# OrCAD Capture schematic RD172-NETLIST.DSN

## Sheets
1 7: size A3
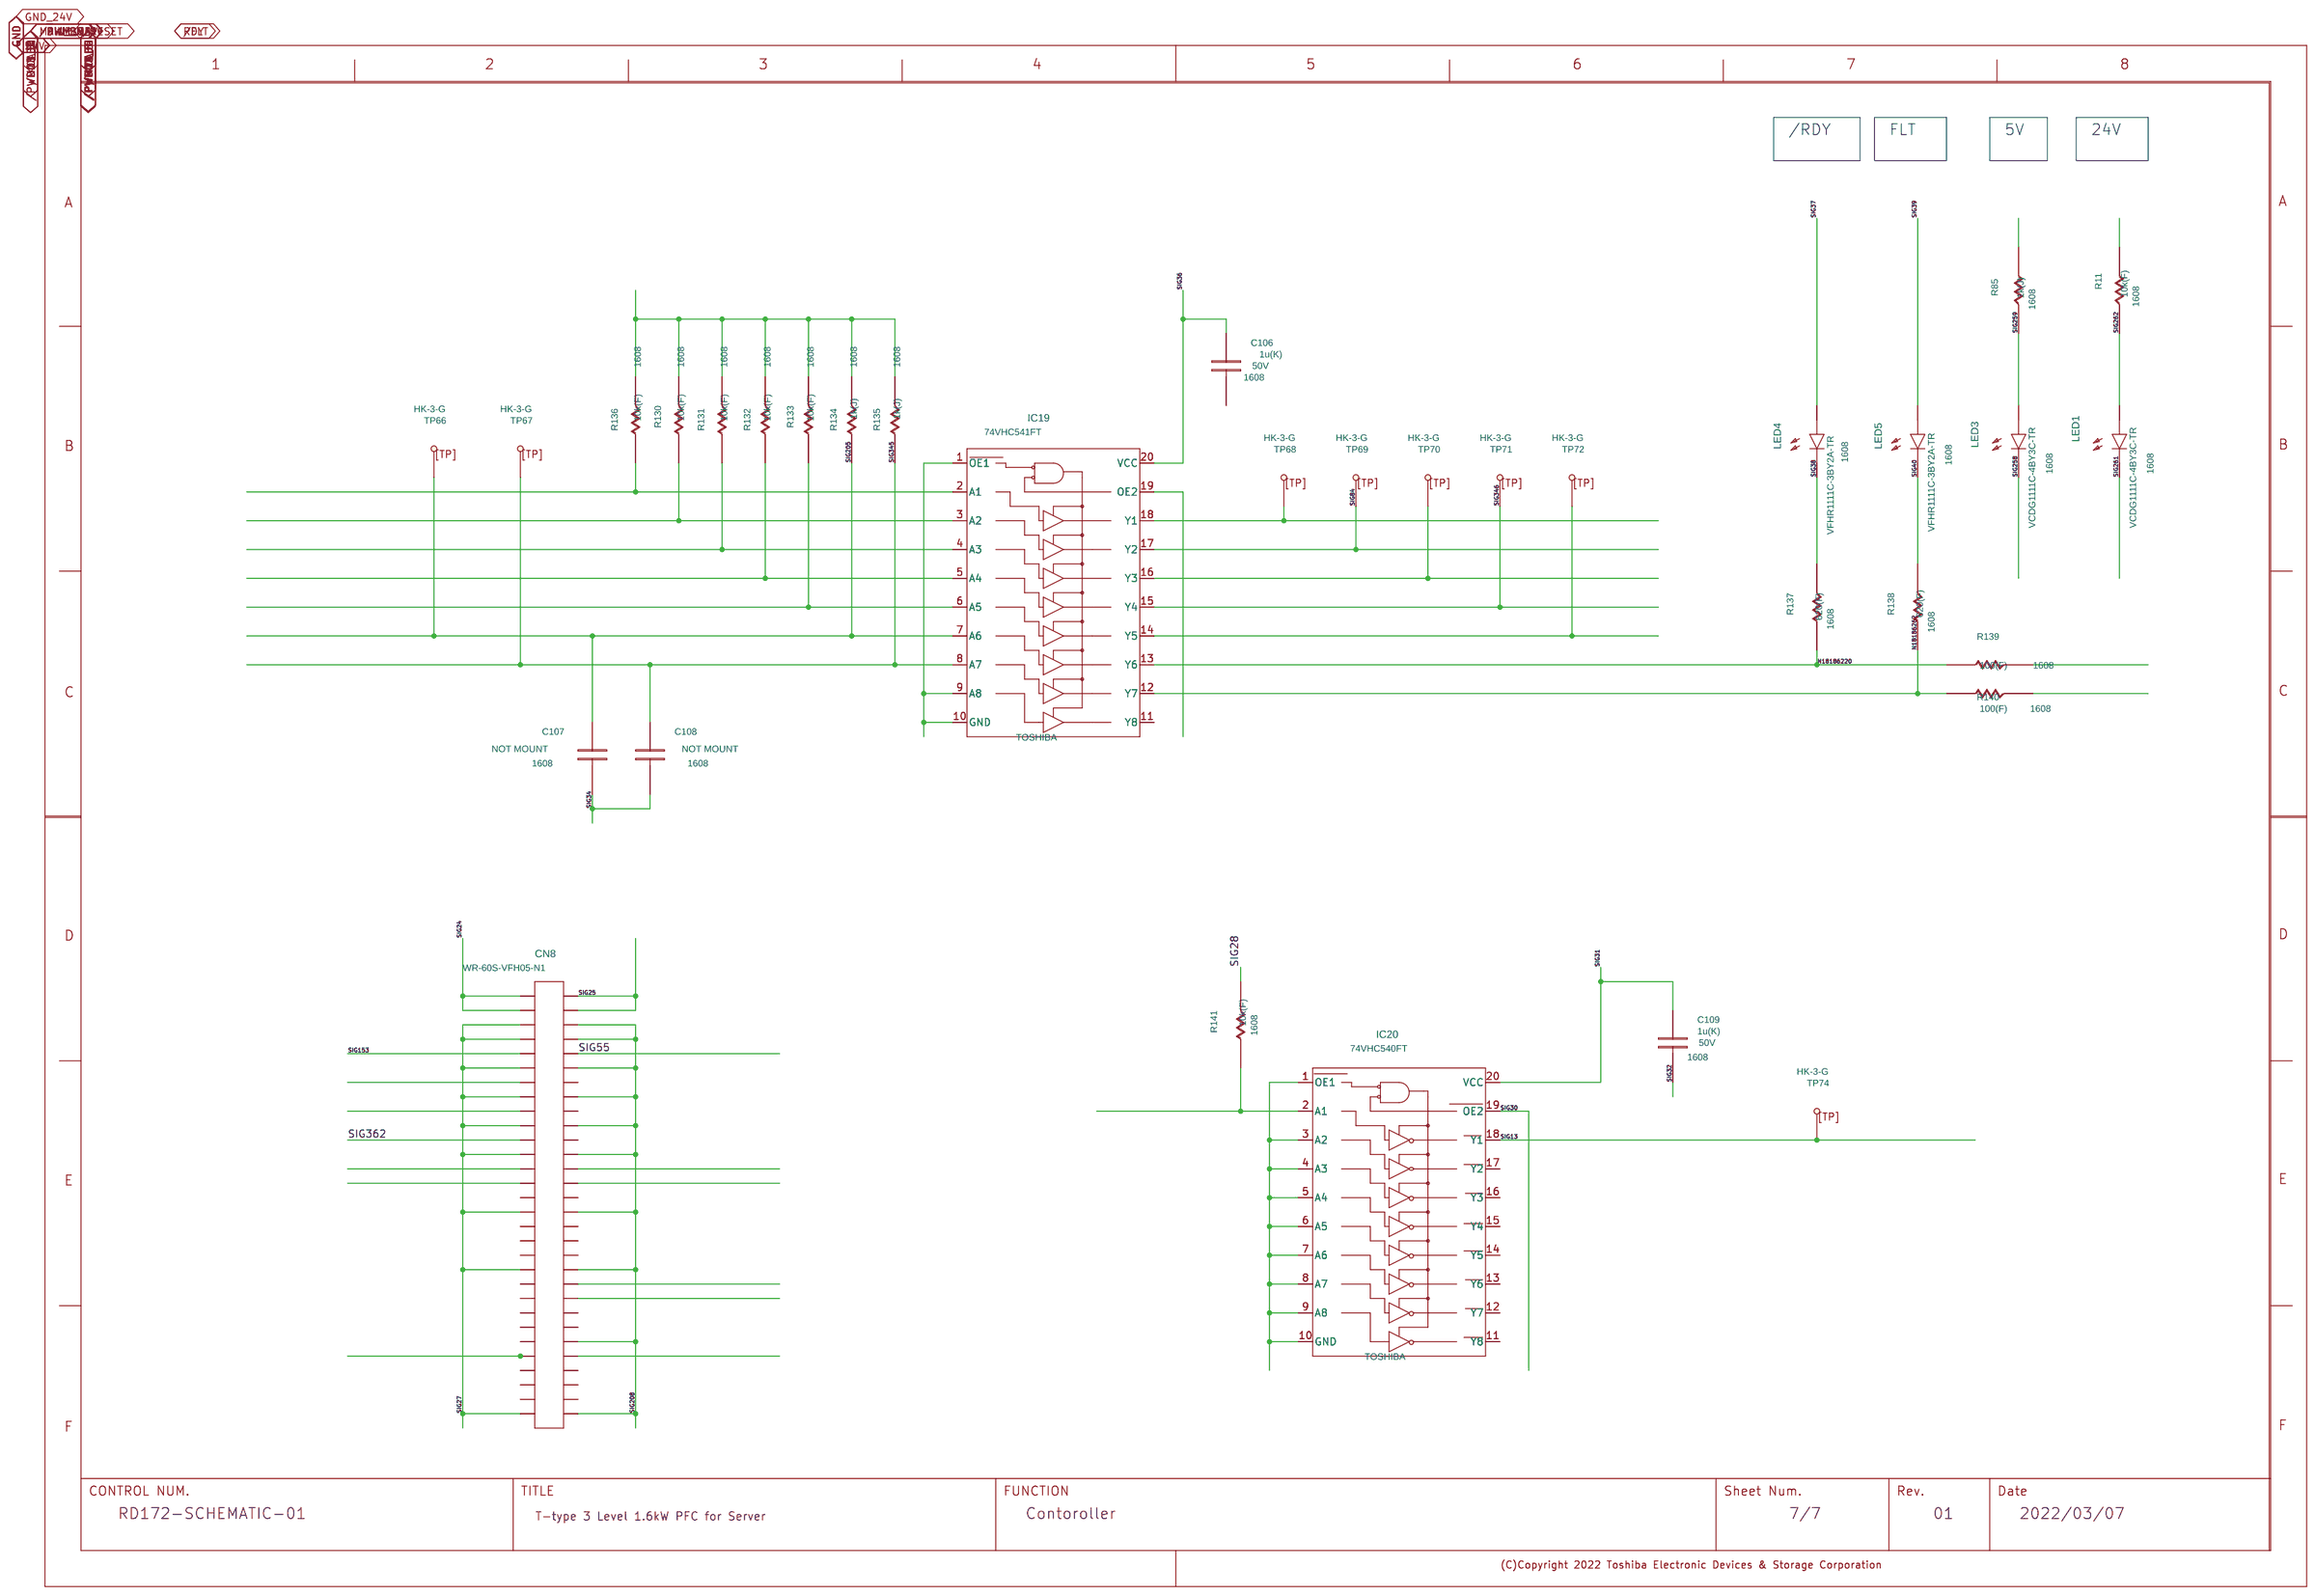
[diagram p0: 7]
2 6: size A3
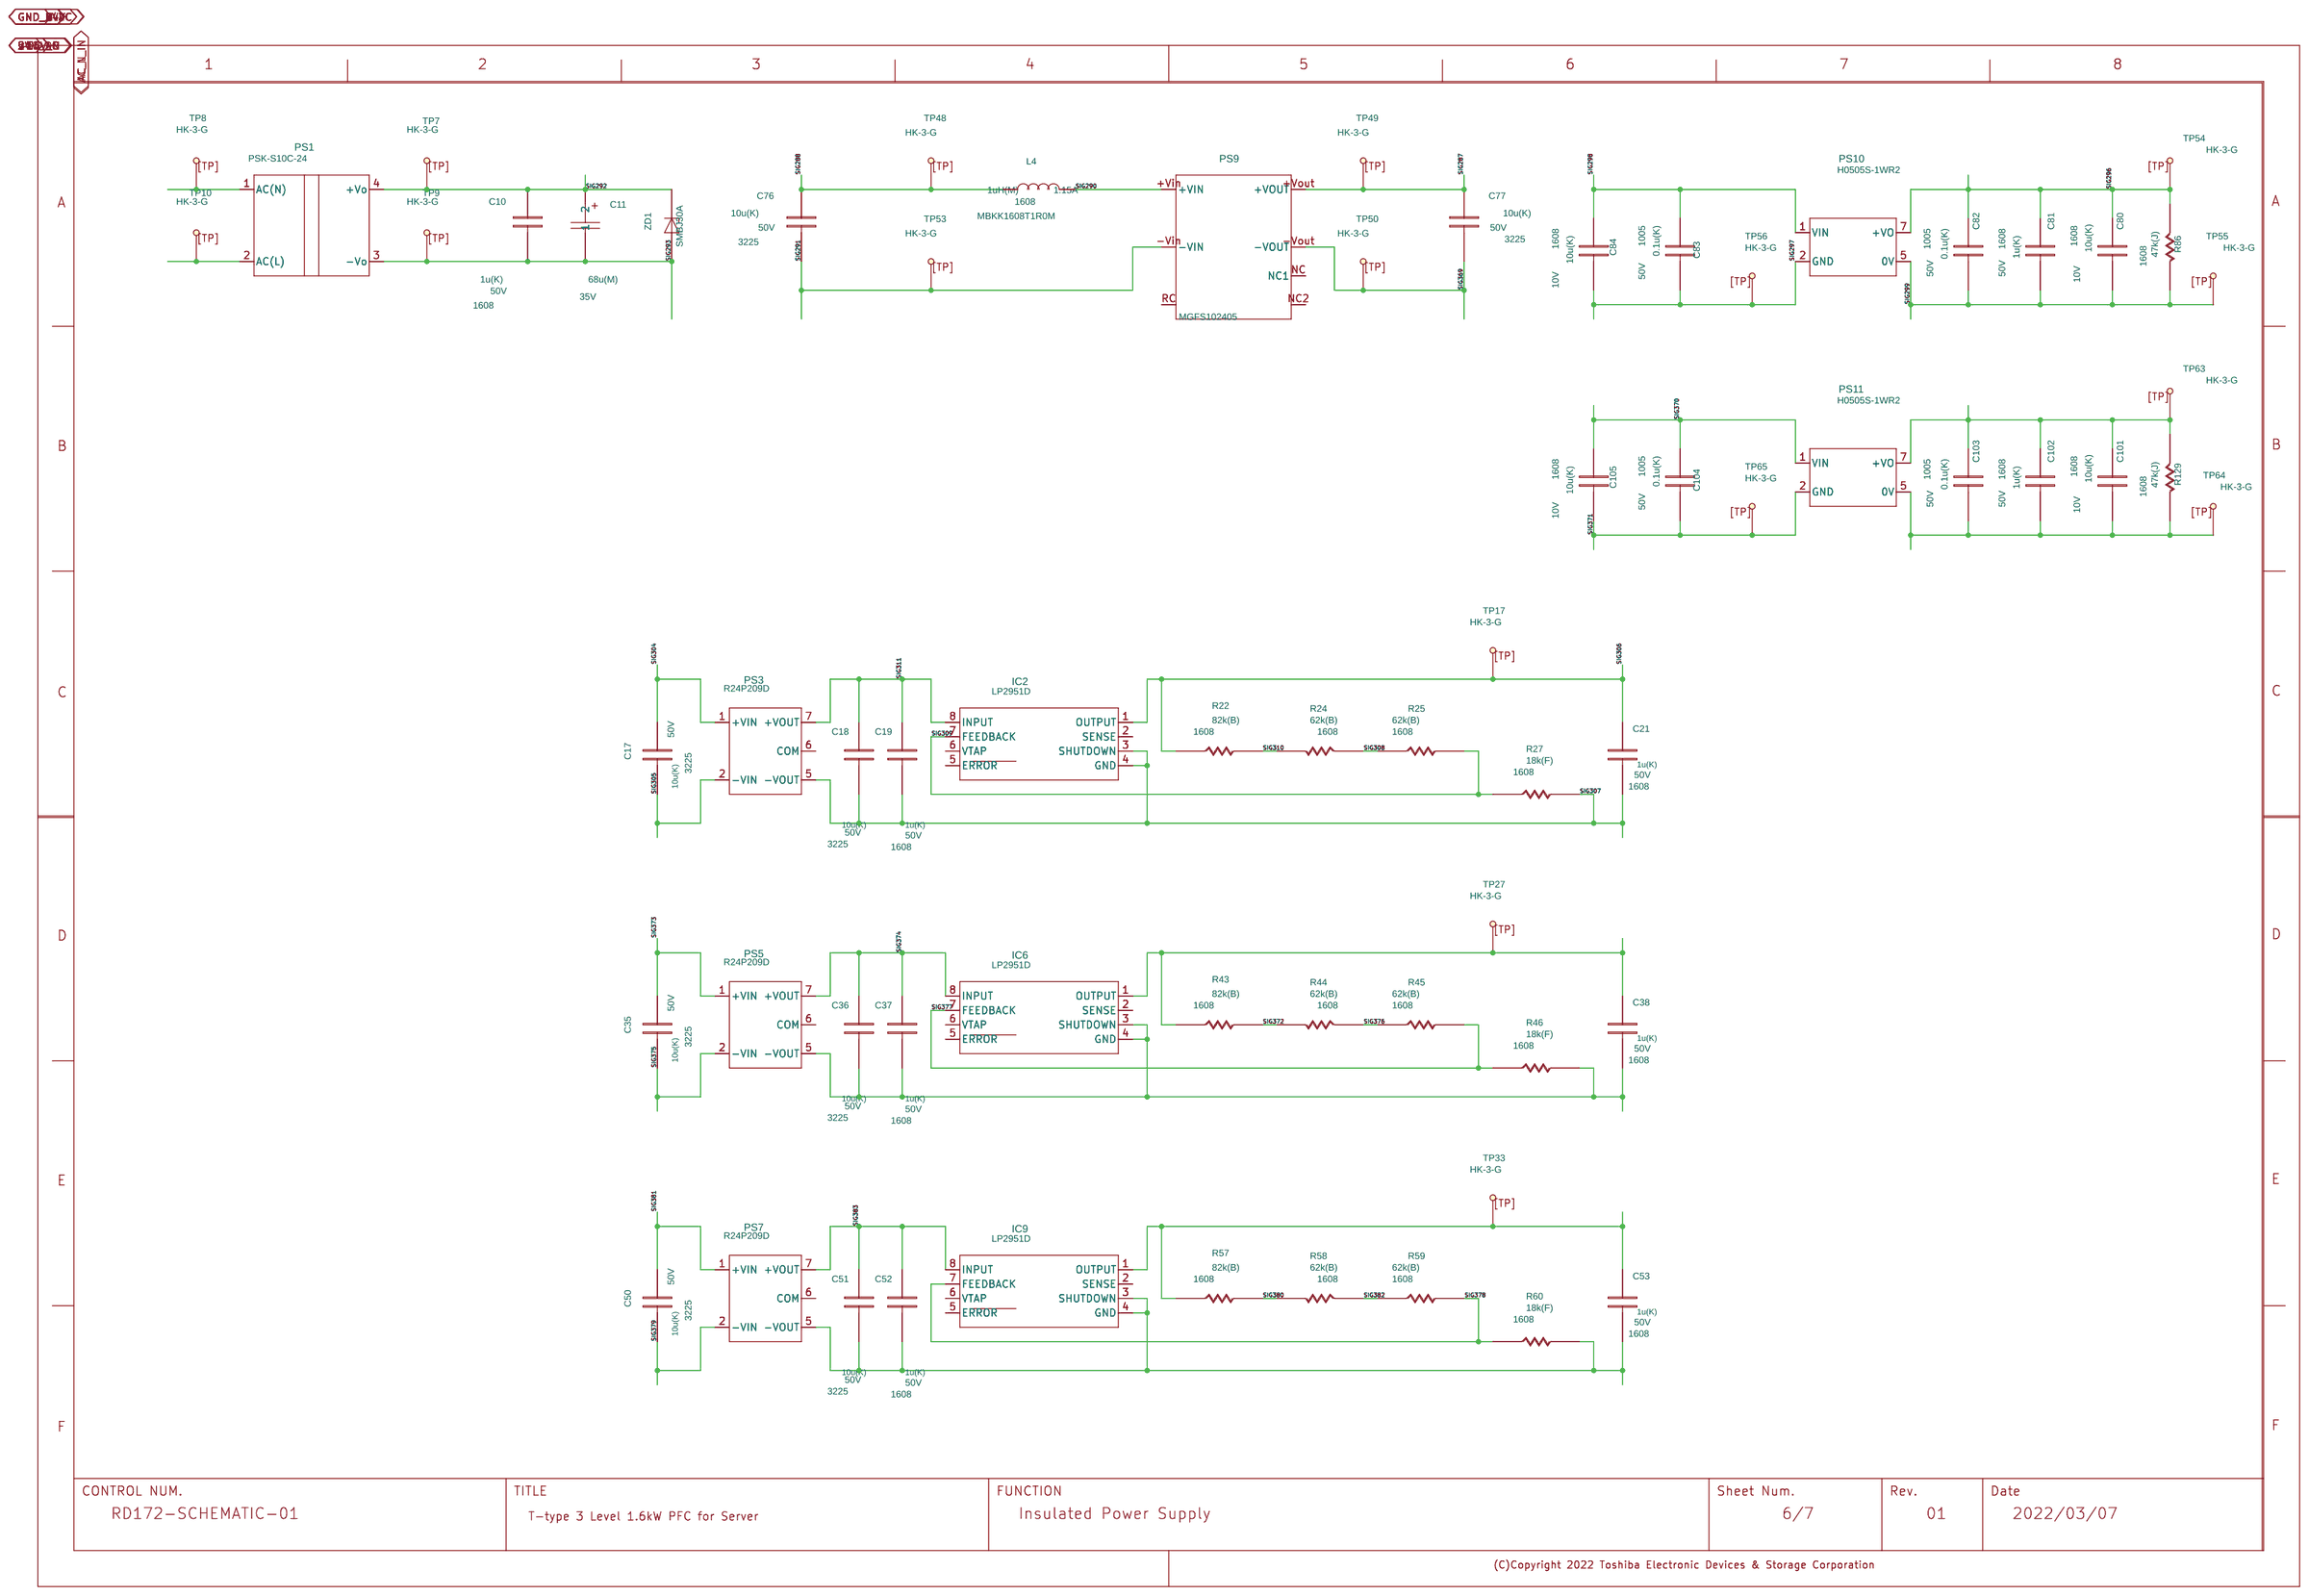
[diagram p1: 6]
3 5: size A3
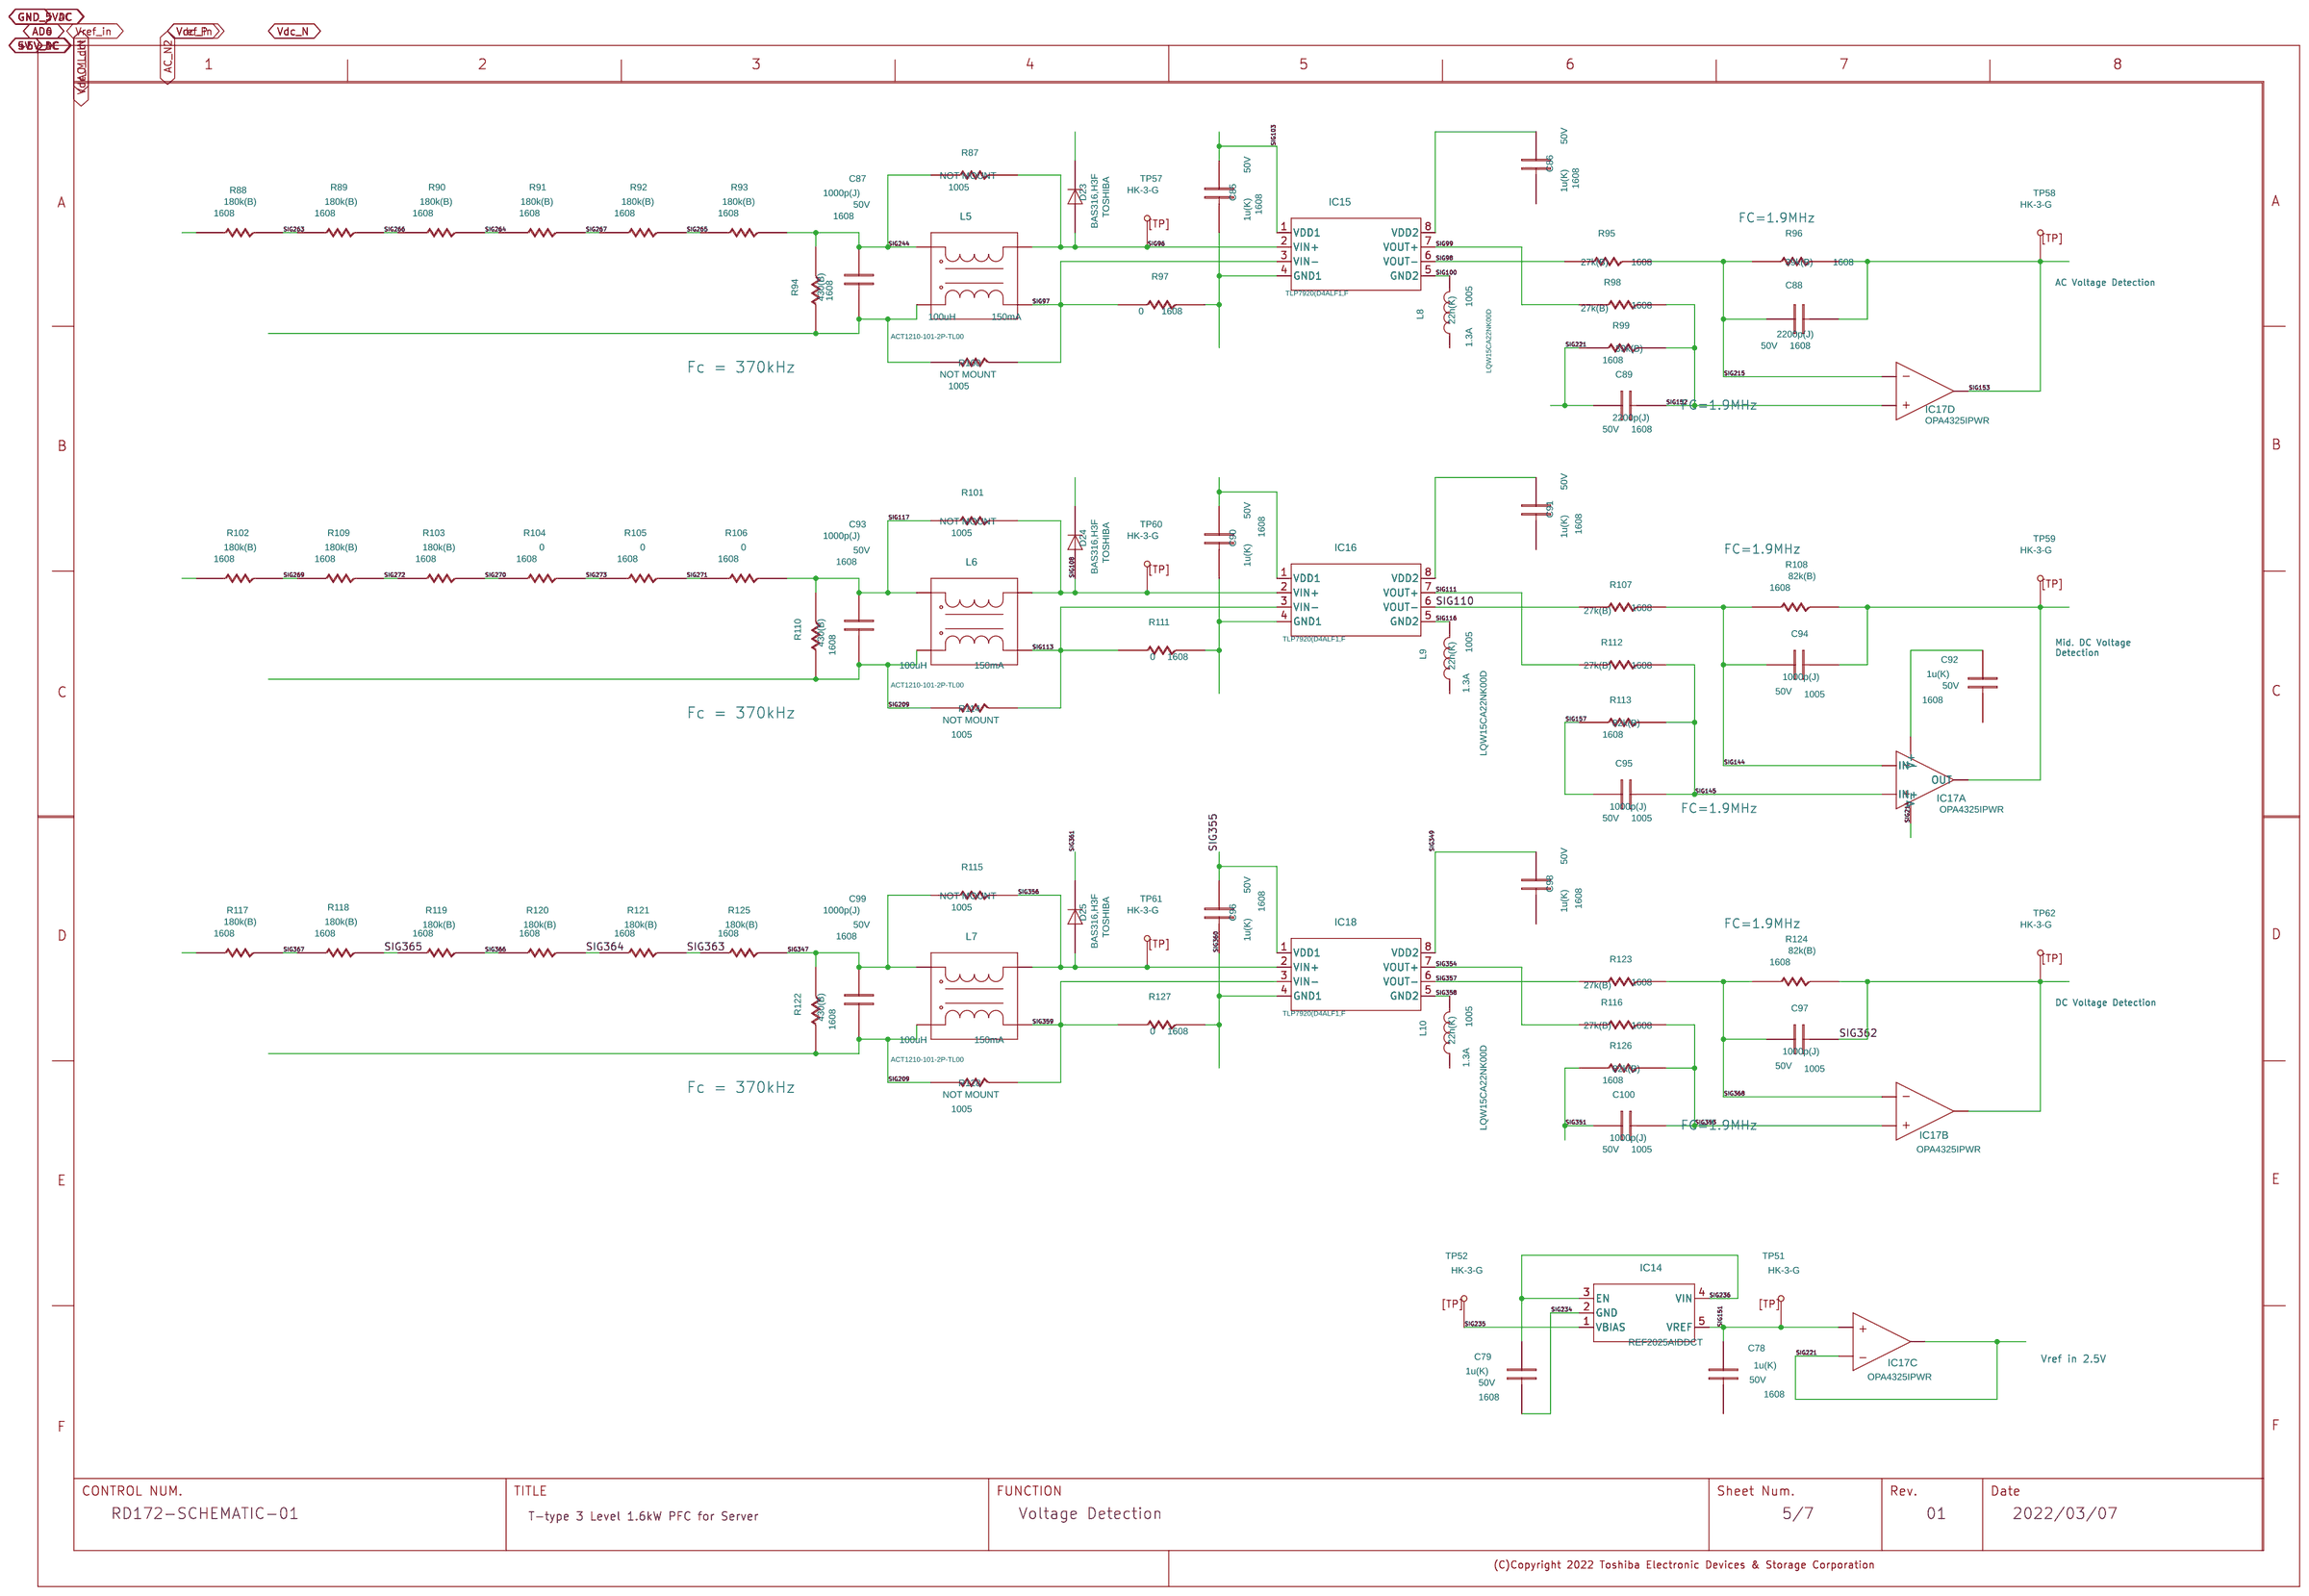
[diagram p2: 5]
4 4: size A3
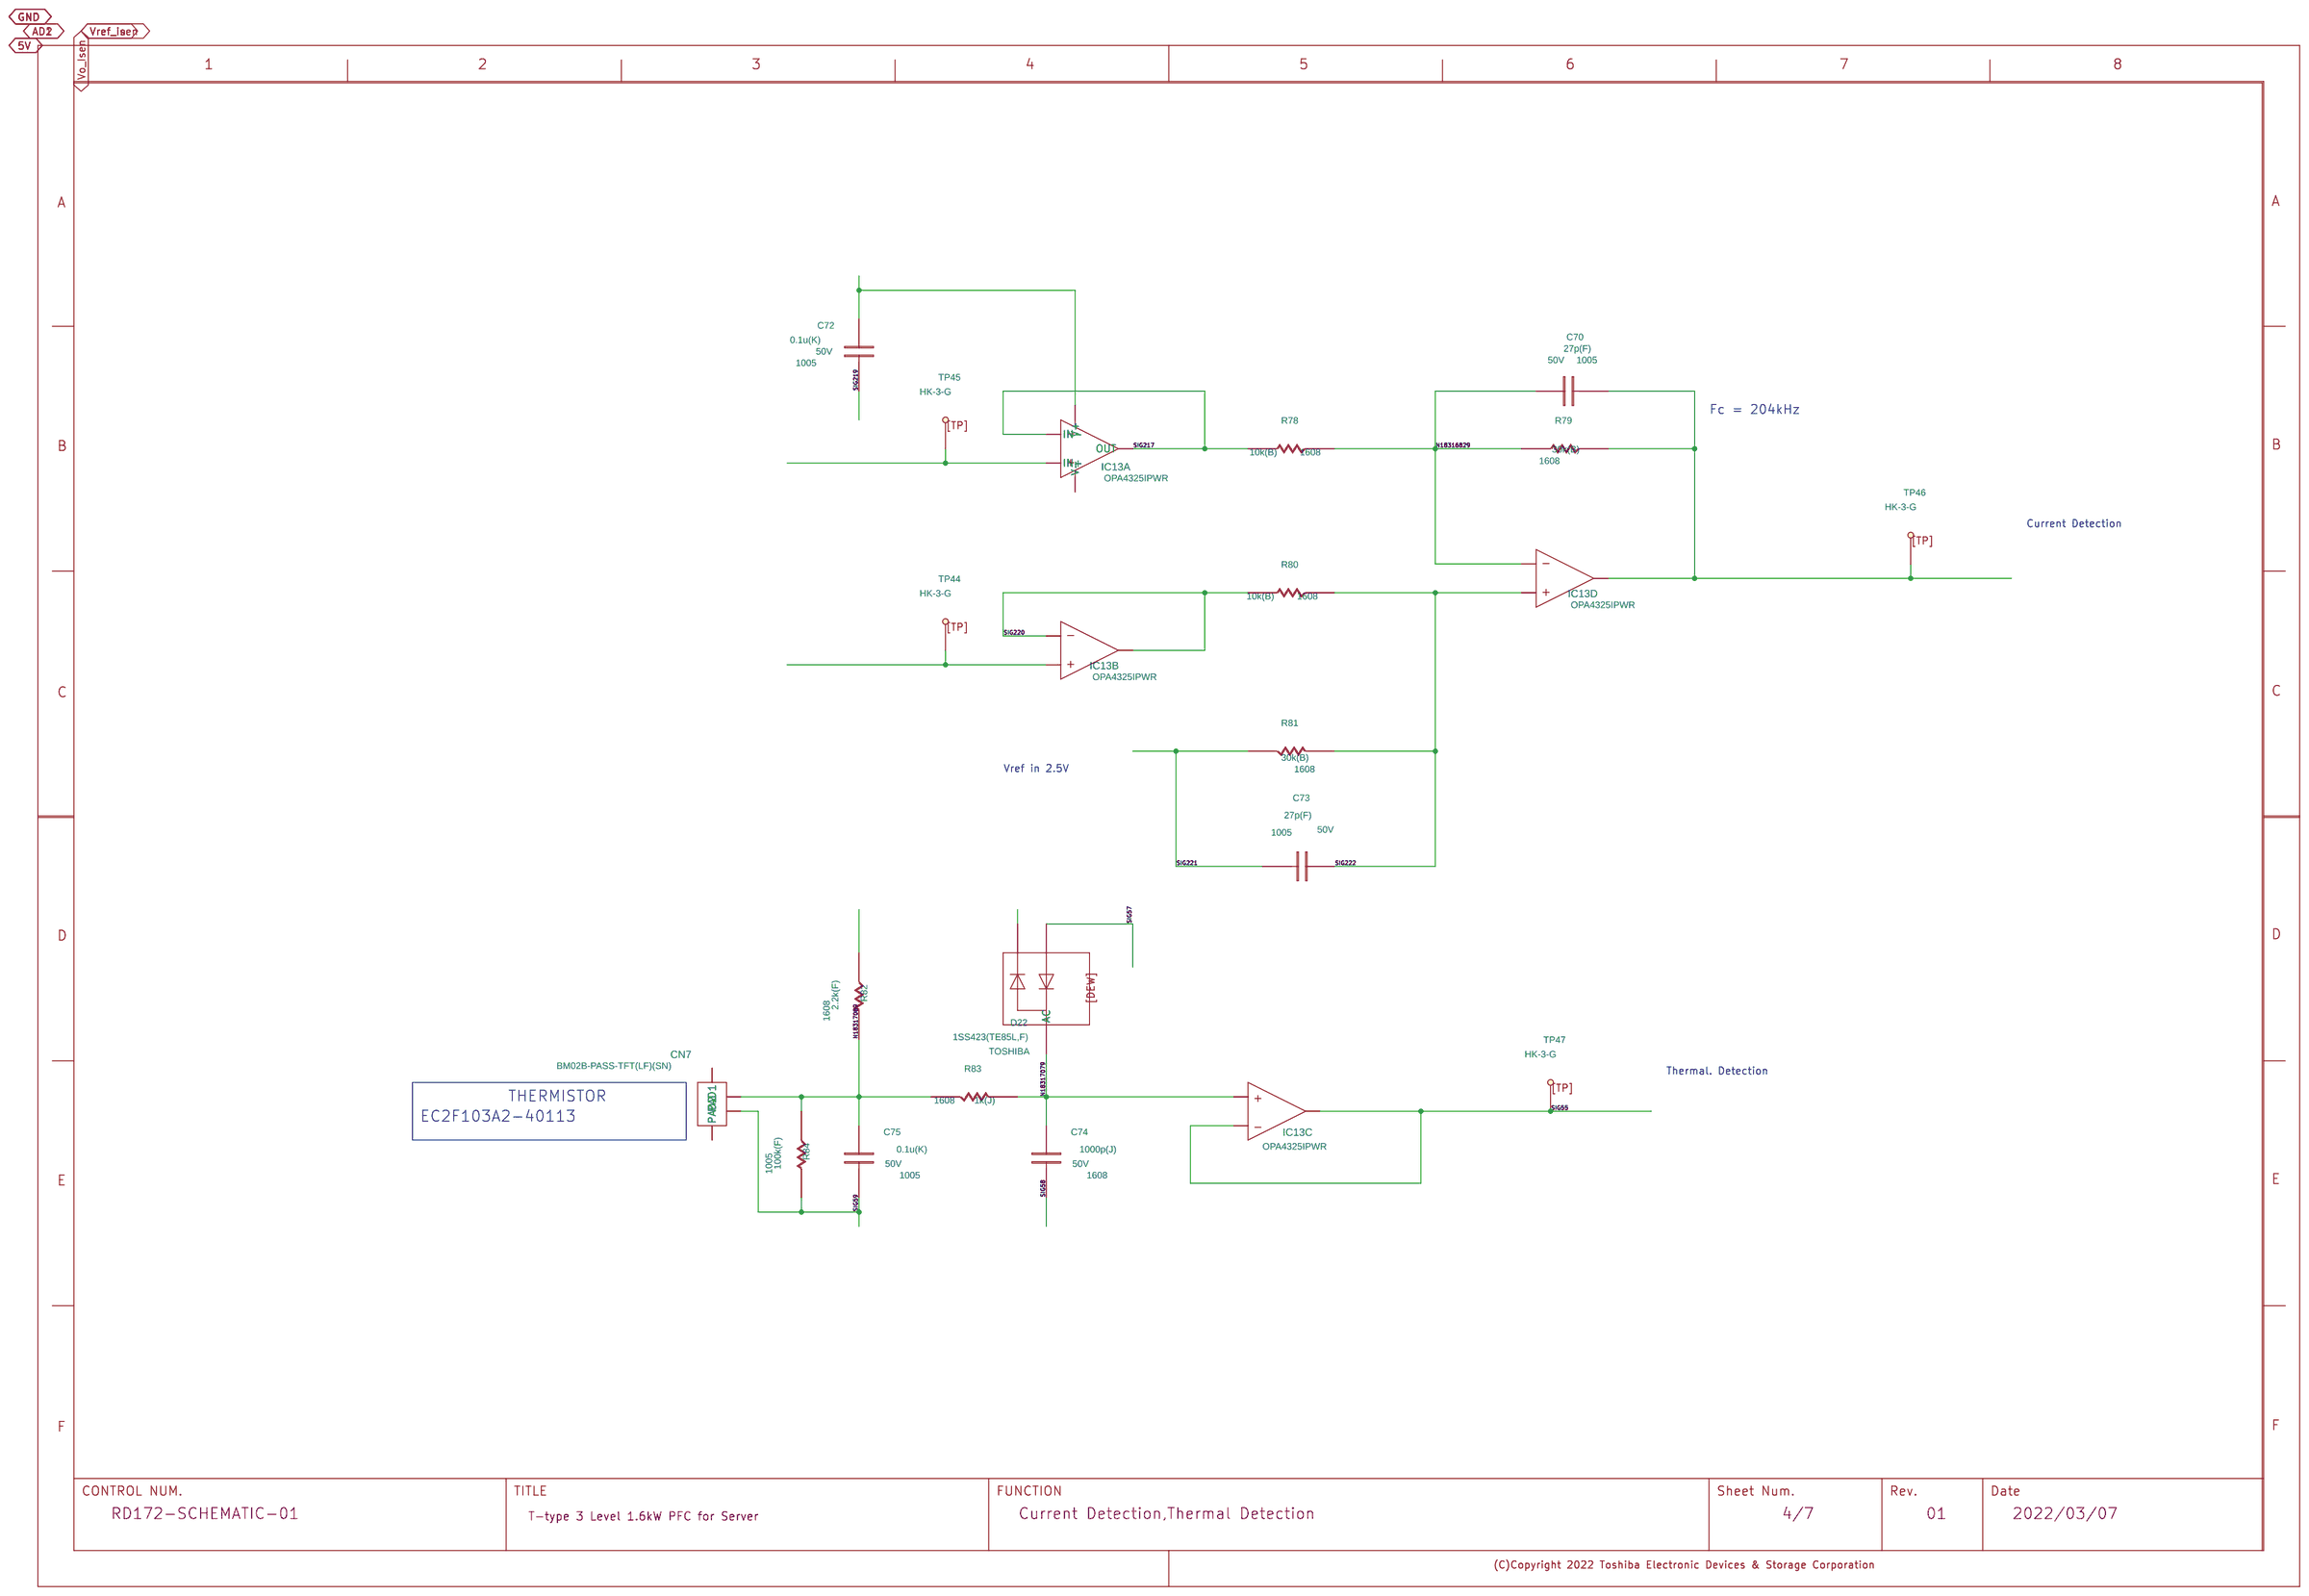
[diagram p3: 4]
5 3: size A3
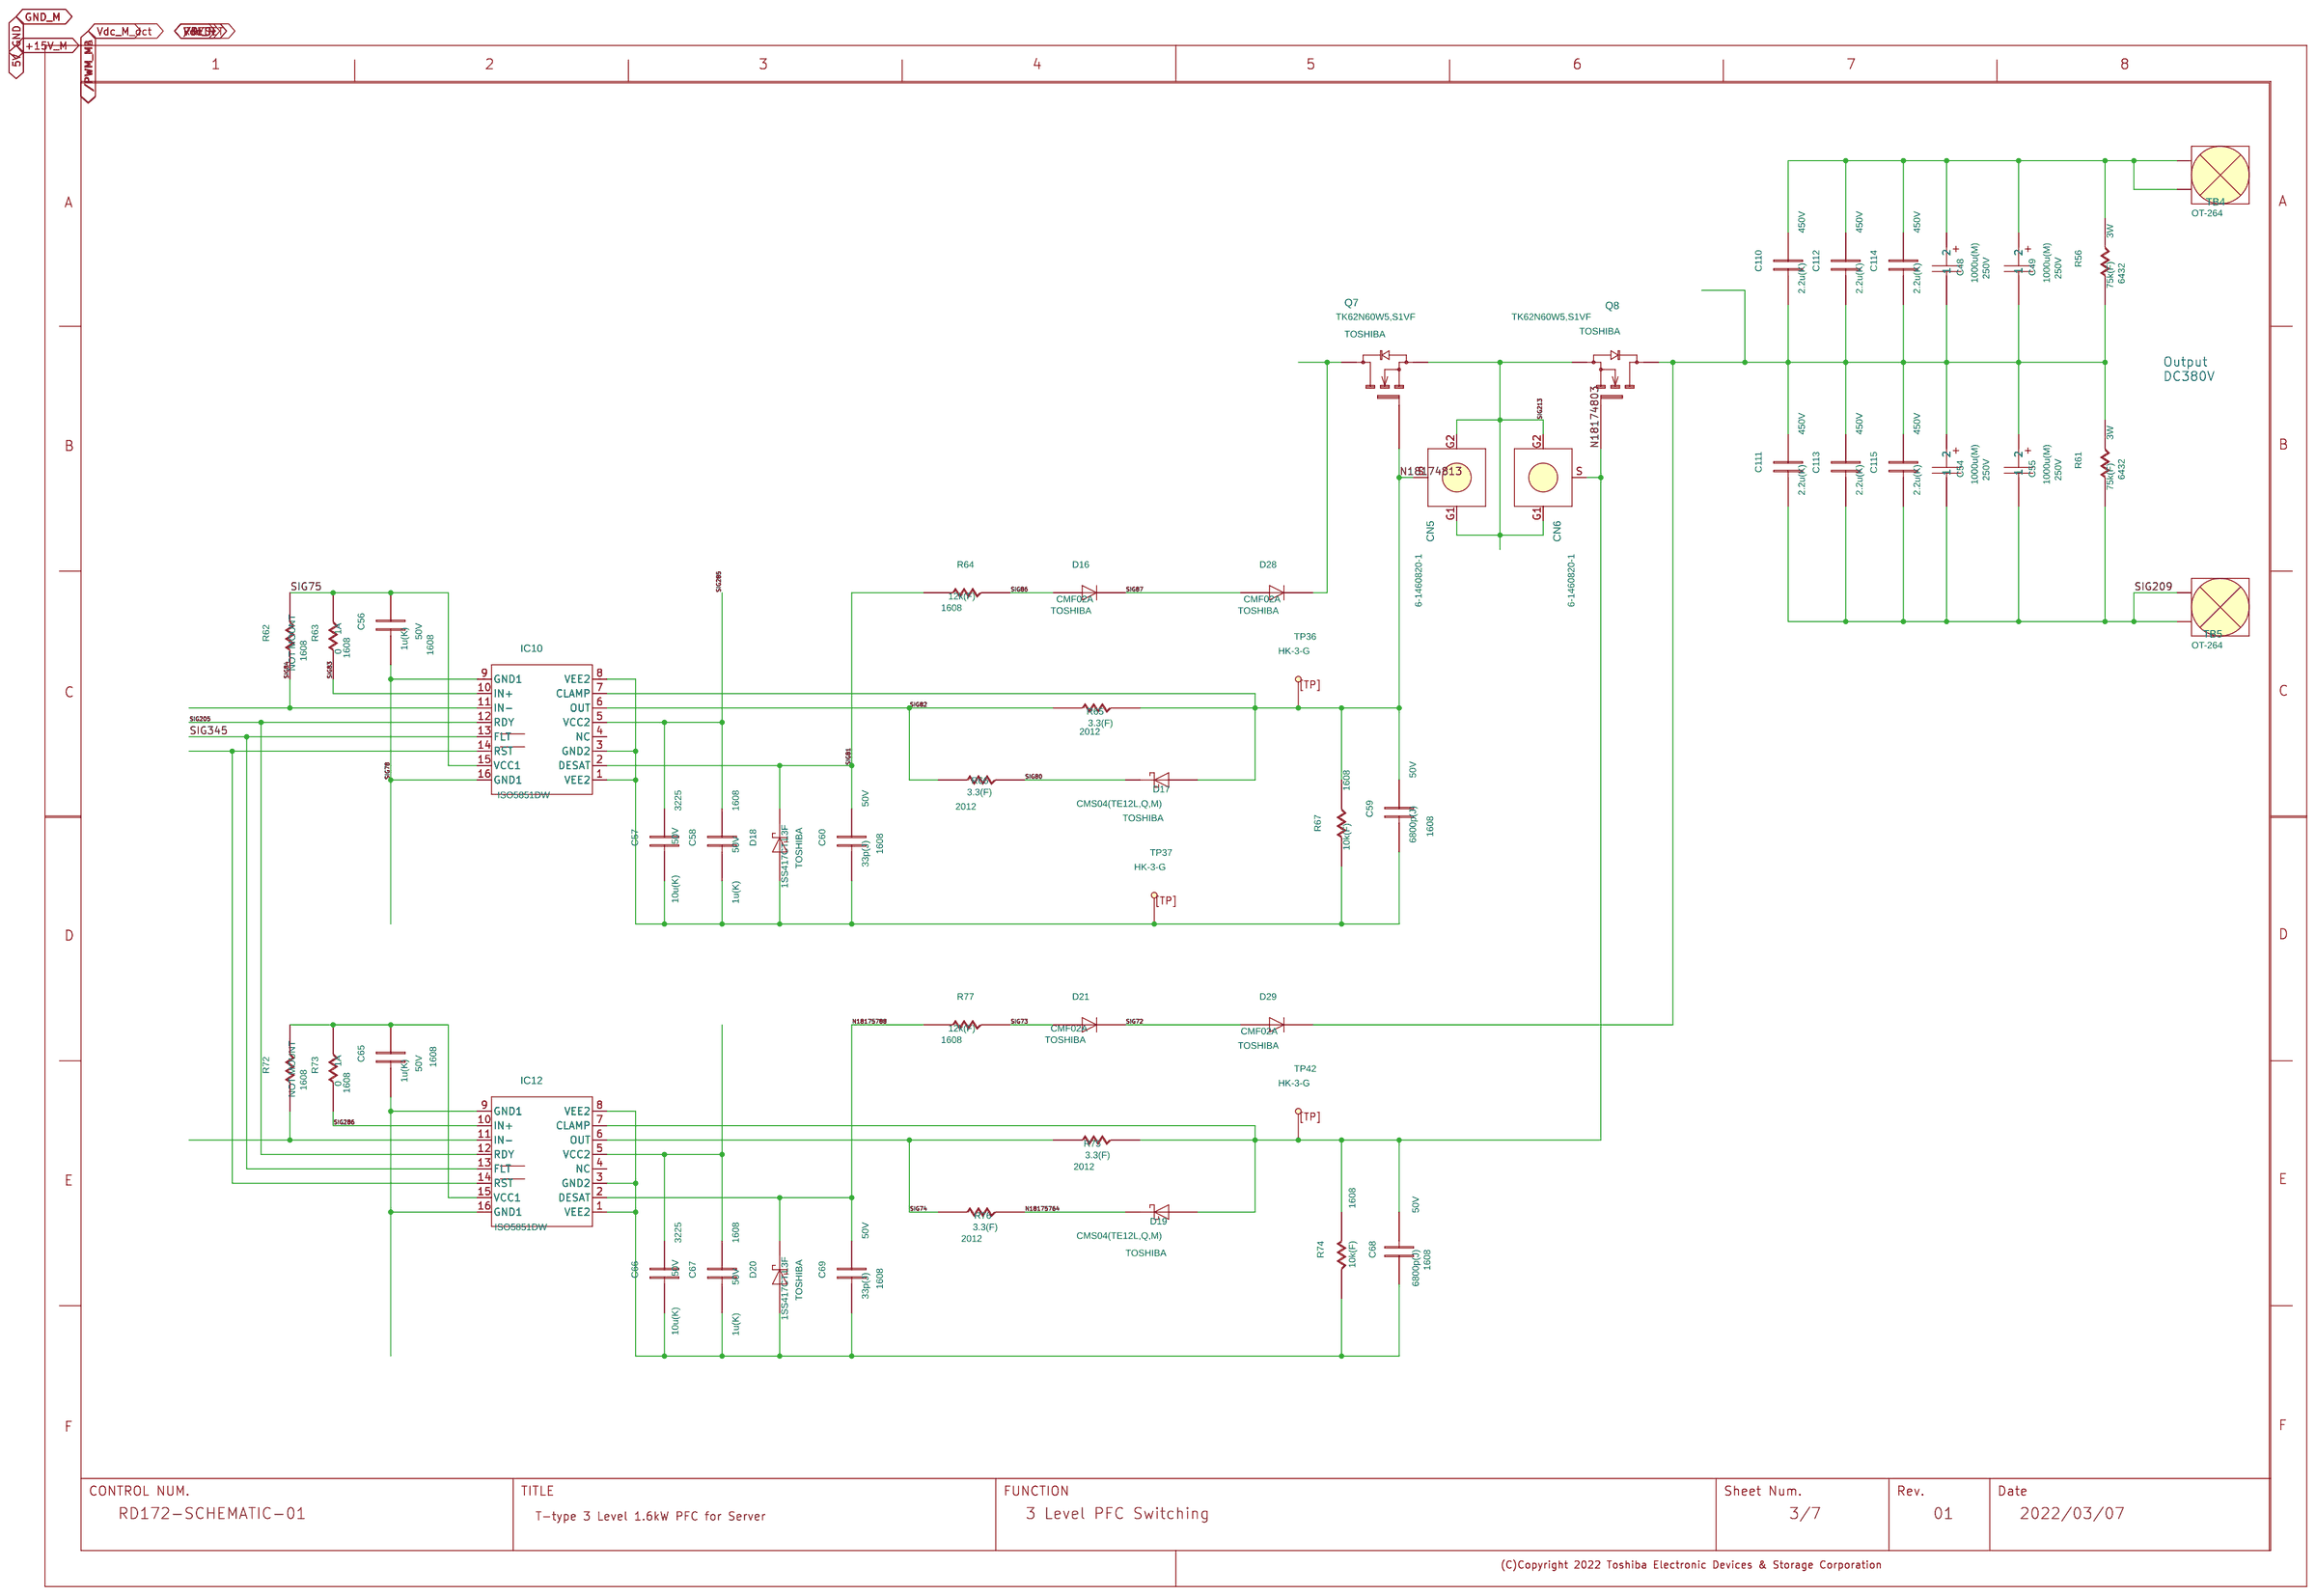
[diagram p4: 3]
6 2: size A3
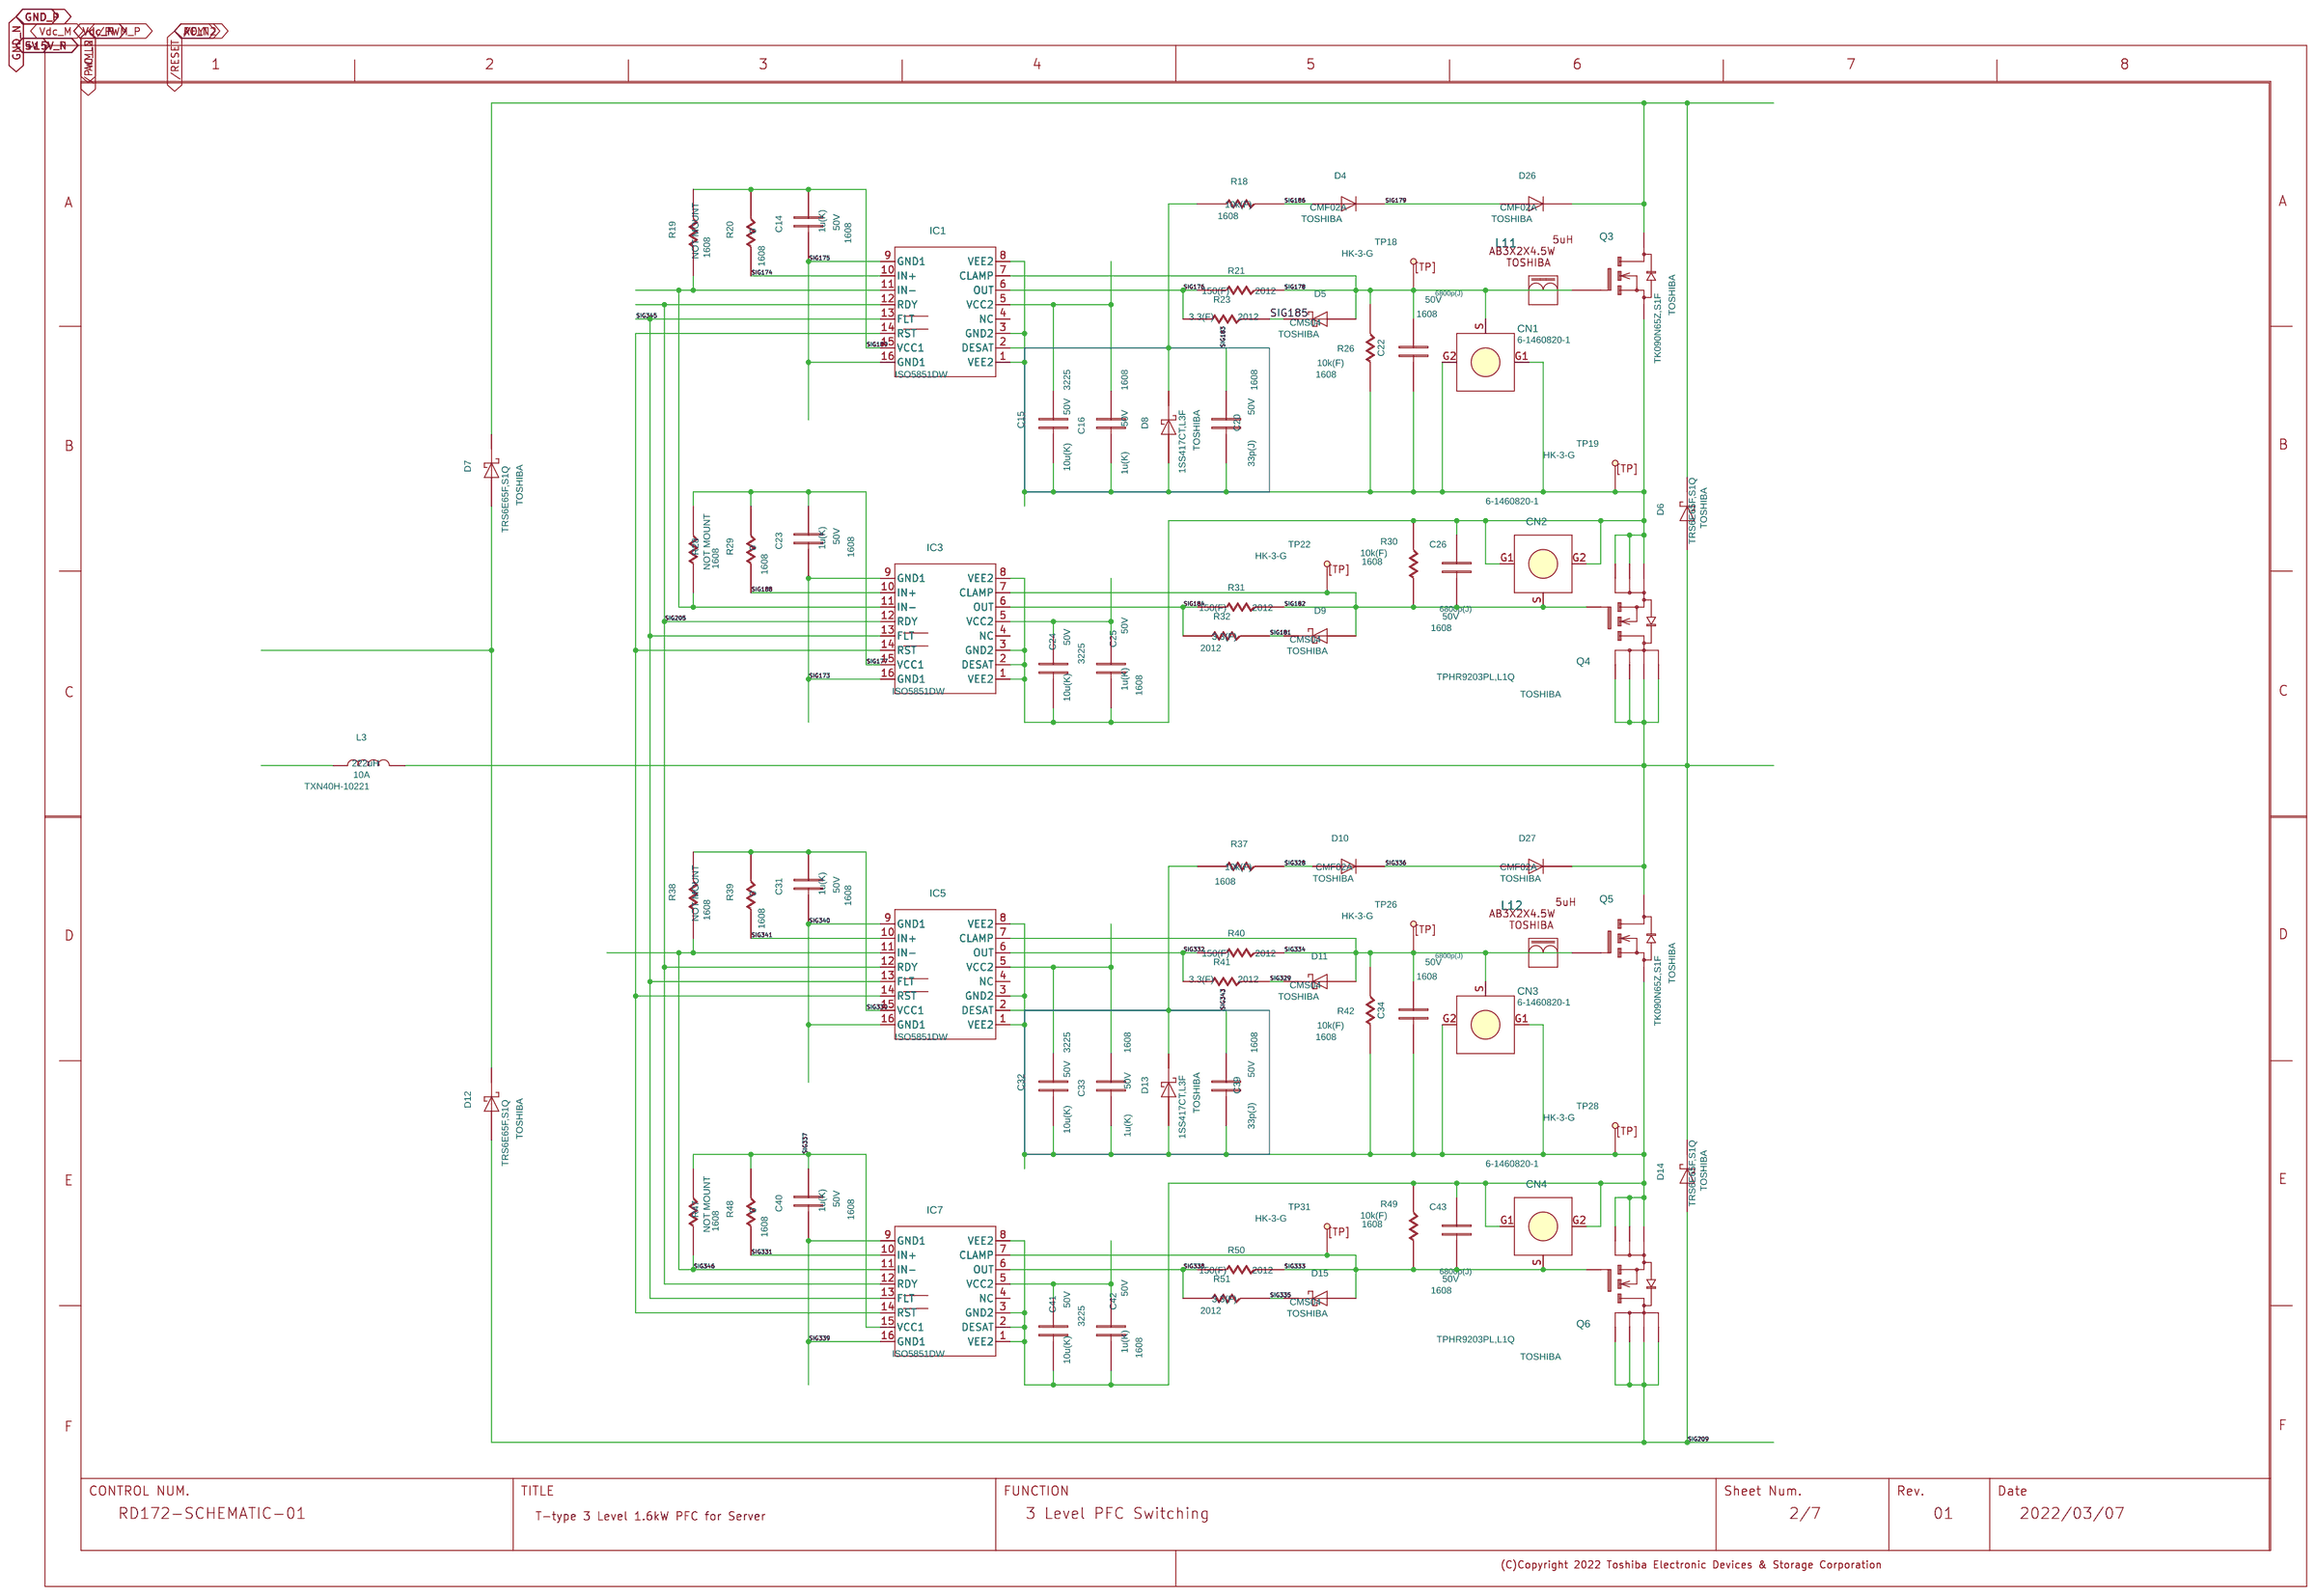
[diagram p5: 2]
7 1: size A3
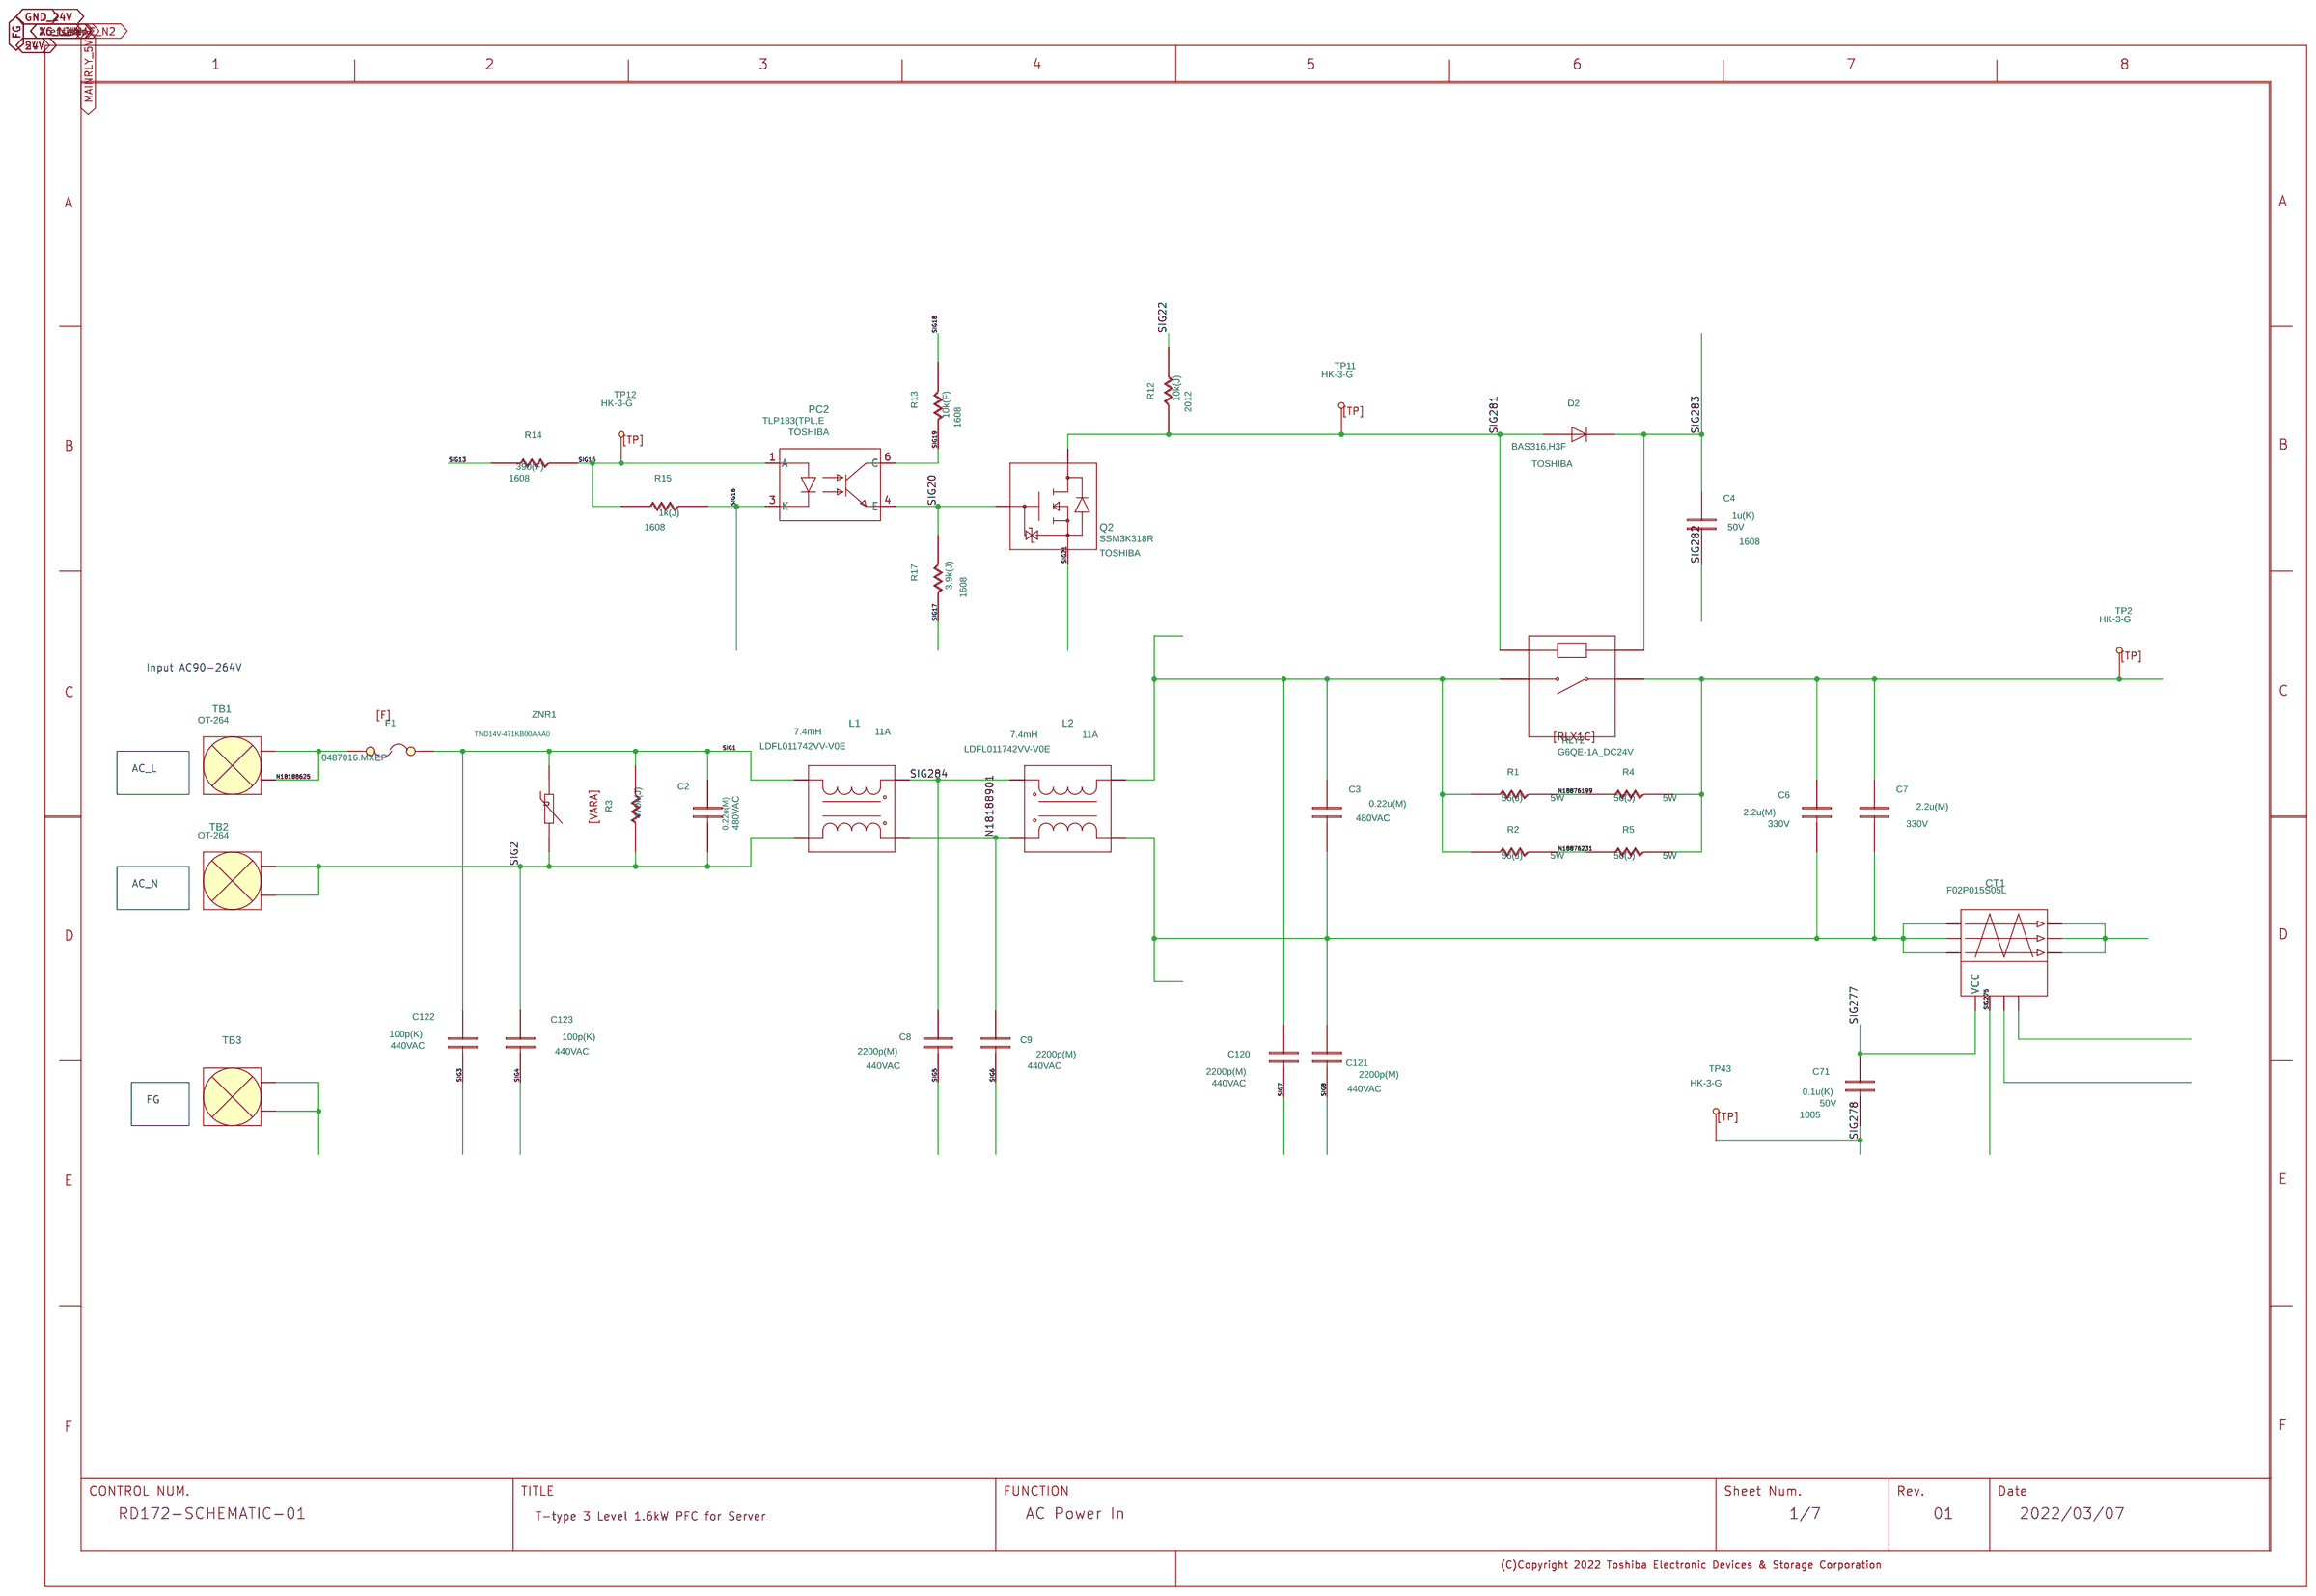
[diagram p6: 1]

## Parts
sheet 1
C2  C
C3  C
C4  C
C6  C
C7  C
C8  C
C9  C
C71  C
C120  C
C121  C
C122  C
C123  C
CT1  F02P015S05L
D2  D
F1  F
L1  LDFL011742VV-V0E
L2  LDFL011742VV-V0E
PC2  TLP183(TPL,E
Q2  SSM3K318R
R1  R
R2  R
R3  R
R4  R
R5  R
R12  R
R13  R
R14  R
R15  R
R17  R
RLY2  RLX1C
TB1  OT-264
TB2  OT-264
TB3  OT-264
TP2  TP
TP11  TP
TP12  TP
TP43  TP
U?#6  WAKU_DEF100
ZNR1  VARA
sheet 2
C14  C
C15  C
C16  C
C20  C
C22  C
C23  C
C24  C
C25  C
C26  C
C31  C
C32  C
C33  C
C34  C
C39  C
C40  C
C41  C
C42  C
C43  C
CN1  6-1460820-1
CN2  6-1460820-1
CN3  6-1460820-1
CN4  6-1460820-1
D4  D
D5  SBD
D6  SBD
D7  SBD
D8  SBD
D9  SBD
D10  D
D11  SBD
D12  SBD
D13  SBD
D14  SBD
D15  SBD
D26  D
D27  D
IC1  ISO5851DW
IC3  ISO5851DW
IC5  ISO5851DW
IC7  ISO5851DW
L3  L
L11  AB3X2X4.5W
L12  AB3X2X4.5W
Q3  TK090N65Z,S1F
Q4  TPHR9203PL,L1Q
Q5  TK090N65Z,S1F
Q6  TPHR9203PL,L1Q
R18  R
R19  R
R20  R
R21  R
R23  R
R26  R
R28  R
R29  R
R30  R
R31  R
R32  R
R37  R
R38  R
R39  R
R40  R
R41  R
R42  R
R47  R
R48  R
R49  R
R50  R
R51  R
TP18  TP
TP19  TP
TP22  TP
TP26  TP
TP28  TP
TP31  TP
U?#5  WAKU_DEF100
sheet 3
C48  CP
C49  CP
C54  CP
C55  CP
C56  C
C57  C
C58  C
C59  C
C60  C
C65  C
C66  C
C67  C
C68  C
C69  C
C110  C
C111  C
C112  C
C113  C
C114  C
C115  C
CN5  6-1460820-1
CN6  6-1460820-1
D16  D
D17  SBD
D18  SBD
D19  SBD
D20  SBD
D21  D
D28  D
D29  D
IC10  ISO5851DW
IC12  ISO5851DW
Q7  TK62N60W5,S1VF
Q8  TK62N60W5,S1VF
R56  R
R61  R
R62  R
R63  R
R64  R
R65  R
R66  R
R67  R
R72  R
R73  R
R74  R
R75  R
R76  R
R77  R
TB4  OT-264
TB5  OT-264
TP36  TP
TP37  TP
TP42  TP
U?#4  WAKU_DEF100
sheet 4
C70  C
C72  C
C73  C
C74  C
C75  C
CN7  BM02B-PASS-TFT(LF)(SN)
D22  DEW
IC13  OPA4325IPWR_4  (sections A,B,C,D)
R78  R
R79  R
R80  R
R81  R
R82  R
R83  R
R84  R
TP44  TP
TP45  TP
TP46  TP
TP47  TP
U?#3  WAKU_DEF100
sheet 5
C78  C
C79  C
C85  C
C86  C
C87  C
C88  C
C89  C
C90  C
C91  C
C92  C
C93  C
C94  C
C95  C
C96  C
C97  C
C98  C
C99  C
C100  C
D23  D
D24  D
D25  D
IC14  REF2025AIDDCT
IC15  TLP7920(D4ALF1,F
IC16  TLP7920(D4ALF1,F
IC17  OPA4325IPWR_4  (sections A,B,C,D)
IC18  TLP7920(D4ALF1,F
L5  ACT1210-101-2P-TL00
L6  ACT1210-101-2P-TL00
L7  ACT1210-101-2P-TL00
L8  L
L9  L
L10  L
R87  R
R88  R
R89  R
R90  R
R91  R
R92  R
R93  R
R94  R
R95  R
R96  R
R97  R
R98  R
R99  R
R100  R
R101  R
R102  R
R103  R
R104  R
R105  R
R106  R
R107  R
R108  R
R109  R
R110  R
R111  R
R112  R
R113  R
R114  R
R115  R
R116  R
R117  R
R118  R
R119  R
R120  R
R121  R
R122  R
R123  R
R124  R
R125  R
R126  R
R127  R
R128  R
TP51  TP
TP52  TP
TP57  TP
TP58  TP
TP59  TP
TP60  TP
TP61  TP
TP62  TP
U?#2  WAKU_DEF100
sheet 6
C10  C
C11  CP
C17  C
C18  C
C19  C
C21  C
C35  C
C36  C
C37  C
C38  C
C50  C
C51  C
C52  C
C53  C
C76  C
C77  C
C80  C
C81  C
C82  C
C83  C
C84  C
C101  C
C102  C
C103  C
C104  C
C105  C
IC2  LP2951D
IC6  LP2951D
IC9  LP2951D
L4  L
PS1  PSK-S10C-24
PS3  R24P209D
PS5  R24P209D
PS7  R24P209D
PS9  MGFS102405
PS10  H0505S-1WR2
PS11  H0505S-1WR2
R22  R
R24  R
R25  R
R27  R
R43  R
R44  R
R45  R
R46  R
R57  R
R58  R
R59  R
R60  R
R86  R
R129  R
TP7  TP
TP8  TP
TP9  TP
TP10  TP
TP17  TP
TP27  TP
TP33  TP
TP48  TP
TP49  TP
TP50  TP
TP53  TP
TP54  TP
TP55  TP
TP56  TP
TP63  TP
TP64  TP
TP65  TP
U?#1  WAKU_DEF100
ZD1  ZD
sheet 7
C106  C
C107  C
C108  C
C109  C
CN8  WR-60S-VFH05-N1
IC19  74VHC541FT
IC20  74VHC540FT
LED1  VCDG1111C-4BY3C-TR
LED3  VCDG1111C-4BY3C-TR
LED4  VFHR1111C-3BY2A-TR
LED5  VFHR1111C-3BY2A-TR
R11  R
R85  R
R130  R
R131  R
R132  R
R133  R
R134  R
R135  R
R136  R
R137  R
R138  R
R139  R
R140  R
R141  R
TP66  TP
TP67  TP
TP68  TP
TP69  TP
TP70  TP
TP71  TP
TP72  TP
TP74  TP
U?#7  WAKU_DEF100

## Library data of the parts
C2 C3 = C: COMP: -C-F339X142248MIP2T0; COMPONENTTYPE: 4; VAL1: 0.22u(M); VAL2: 480VAC
C4 C10 C14 C16 C19 C21 C23 C25 C31 C33 C37 C38 C40 C42 C52 C53 C56 C58 C65 C67 C78 C79 C81 C85 C86 C90-C92 C96 C98 C102 C106 C109 = C: COMP: -C-UMK107AB7105KA-T; COMPONENTTYPE: 4; SIZECODESMD: 1608; VAL1: 1u(K); VAL2: 50V
C6 C7 = C: COMP: -C-B32914A3225M000; COMPONENTTYPE: 4; VAL1: 2.2u(M); VAL2: 330V
C8 C9 C120 C121 = C: COMP: -C-CD45-E2GA222M-VKA; COMPONENTTYPE: 4; VAL1: 2200p(M); VAL2: 440VAC
C71 C72 C75 C82 C83 C103 C104 = C: COMP: -C-UMK105BJ104KV-F; COMPONENTTYPE: 4; SIZECODESMD: 1005; VAL1: 0.1u(K); VAL2: 50V
C122 C123 = C: COMP: -C-CD45-B2GA101K-VKA; COMPONENTTYPE: 4; VAL1: 100p(K); VAL2: 440VAC
CT1 = F02P015S05L: COMP: -CT-F02P015S05L_PIN; COMPONENTTYPE: 4
D2 D23-D25 = D: COMP: -D-BAS316_H3F_AC; COMPONENTTYPE: 4; USERCOMPTEXT3: TOSHIBA; VAL1: BAS316,H3F; VAL3: BAS316,H3F
F1 = F: COMP: -F-0487016MXEP; COMPONENTTYPE: 4; VAL1: 0487016.MXEP; VAL3: 0487016.MXEP
L1 L2 = LDFL011742VV_V0E: COMP: -L-LDFL011742VV-V0E; COMPONENTTYPE: 4; INSTANCENAME: INS18188789; SAVECOUNT: 1; UPDATEDATE: 2021/12/22; UPDATETIME: 16:53:58; VAL1: 7.4mH; VAL2: 11A
PC2 = TLP183_TPL_E: COMP: -PC-TLP183_TPL_E; COMPONENTTYPE: 4; USERCOMPTEXT3: TOSHIBA
Q2 = SSM3K318R: COMP: -Q-SSM3K318R_LF; COMPONENTTYPE: 4; USERCOMPTEXT3: TOSHIBA
R1 R2 R4 R5 = R: COMP: -R-SQMW556RJ; COMPONENTTYPE: 4; VAL1: 56(J); VAL2: 5W
R3 = R: COMP: -R-RCR60C474J; COMPONENTTYPE: 4; VAL1: 470k(J); VAL2: 1W
R12 = R: COMP: -R-RK73B2ATTD103J; COMPONENTTYPE: 4; SIZECODESMD: 2012; VAL1: 10k(J); VAL2: 250mW
R11 R13 R18 R26 R30 R37 R42 R49 R67 R74 R130-R133 R136 R141 = R: COMP: -R-ERJ3EKF1002V; COMPONENTTYPE: 4; SIZECODESMD: 1608; VAL1: 10k(F); VAL2: 100mW
R14 = R: COMP: -R-ERJ3EKF3900V; COMPONENTTYPE: 4; SIZECODESMD: 1608; VAL1: 390(F); VAL2: 100mW
R15 R83 R85 R134 R135 = R: COMP: -R-RK73B1JTTD102J; COMPONENTTYPE: 4; SIZECODESMD: 1608; VAL1: 1k(J); VAL2: 125mW
R17 = R: COMP: -R-RK73B1JTTD392J; COMPONENTTYPE: 4; SIZECODESMD: 1608; VAL1: 3.9k(J); VAL2: 100mW
RLY2 = RLX1C: COMP: -RL-G6QE-1A_DC24; COMPONENTTYPE: 4; VAL1: G6QE-1A_DC24V; VAL3: G6QE-1A_DC24V
TB1 = OT_264: COMP: -TB-OT-264; COMPONENTTYPE: 4; INSTANCENAME: INS18188586; PART TYPE: Terminal Block; REFERENCE TEMPLATE: TB; SAVECOUNT: 1; SIZE: 1; UPDATEDATE: 2021/12/22; UPDATETIME: 16:53:54
TB2 = OT_264: COMP: -TB-OT-264; COMPONENTTYPE: 4; INSTANCENAME: INS18188886; PART TYPE: Terminal Block; REFERENCE TEMPLATE: TB; SAVECOUNT: 1; SIZE: 1; UPDATEDATE: 2021/12/22; UPDATETIME: 16:53:54
TB3 = OT_264: COMP: -TB-OT-264; COMPONENTTYPE: 4
TP2 TP7-TP12 TP17-TP19 TP22 TP26-TP28 TP31 TP33 TP36 TP37 TP42-TP72 TP74 = TP: COMP: -TP-HK-3-G; COMPONENTTYPE: 4; VAL1: HK-3-G; VAL3: HK-3-G
U?#6 = WAKU_DEF100: COMPONENTTYPE: 2; DATE: 2022/03/07; DRAWINGNUMBER: RD172-SCHEMATIC-01; FUNCTION: AC Power In; REVISION: 01; SAVEAREA0: 148187,-66180,486823,89919; SAVECOUNT: 6; SHEETNUMBER: 1/7; TITLE: T-type 3 Level 1.6kW PFC for Server; UPDATEDATE: 2022/03/07; UPDATETIME: 09:34:25
ZNR1 = VARA: COMP: -ZNR-TND14V-471KB00AAA0; COMPONENTTYPE: 4; VAL1: TND14V-471KB00AAA0; VAL3: TND14V-471KB00AAA0
C15 C17 C18 C24 C32 C35 C36 C41 C50 C51 C57 C66 C76 C77 = C: COMP: -C-UMK325AB7106KM-T; COMPONENTTYPE: 4; SIZECODESMD: 3225; VAL1: 10u(K); VAL2: 50V
C20 C39 C60 C69 = C: COMP: -C-CGA3E2C0G1H330J080AA; COMPONENTTYPE: 4; SIZECODESMD: 1608; VAL1: 33p(J); VAL2: 50V
C22 C26 C34 C43 C59 C68 = C: COMP: -C-GRM1885C1H682JA01D; COMPONENTTYPE: 4; SIZECODESMD: 1608; VAL1: 6800p(J); VAL2: 50V
CN1-CN6 = 6_1460820_1: COMP: -CN-6-1460820-1; COMPONENTTYPE: 4
D4 D10 D16 D21 D26-D29 = D: COMP: -D-CMF05_AC; COMPONENTTYPE: 4; USERCOMPTEXT3: TOSHIBA; VAL1: CMF02A; VAL3: CMF02A
D5 D9 D11 D15 = SBD: COMP: -D-CMS04_TE12L_Q_AC; COMPONENTTYPE: 4; USERCOMPTEXT3: TOSHIBA; VAL1: CMS04(TE12L,Q,M); VAL3: CMS04
D6 D7 D12 D14 = SBD: COMP: -D-TRS6E65F_S1Q_AC; COMPONENTTYPE: 4; USERCOMPTEXT3: TOSHIBA; VAL1: TRS6E65F,S1Q; VAL3: TRS6E65F,S1Q
D8 D13 D18 D20 = SBD: COMP: -D-1SS417CTL3F_AC; COMPONENTTYPE: 4; USERCOMPTEXT3: TOSHIBA; VAL1: 1SS417CT,L3F; VAL3: 1SS417CT,L3F
IC1 IC3 IC5 IC7 IC10 IC12 = ISO5851DW: COMP: -IC-ISO5851DWR; COMPONENTTYPE: 4
L3 = L: COMP: -L-TXN40H-10221; COMPONENTTYPE: 4; VAL1: 222uH; VAL2: 10A; VAL3: TXN40H-10221
L11 L12 = AB3X2X4_5W: COMPONENTTYPE: 0; INSTANCENAME: INS19006446; SAVECOUNT: 1; UPDATEDATE: 2021/12/22; UPDATETIME: 16:53:53; USERCOMPTEXT3: TOSHIBA; VAL1: 5uH
Q3 Q5 = TK090N65Z,S1F: COMP: -Q-TK090N65Z; COMPONENTTYPE: 4; INSTANCENAME: INS18162118; USERCOMPTEXT3: TOSHIBA
Q4 Q6 = TPHR9203PL,L1Q: COMP: -Q-TPHR9203PL_GDS; COMPONENTKIND: 102; COMPONENTTYPE: 4; INSTANCENAME: INS18653275; USERCOMPTEXT3: TOSHIBA
R19 R28 R38 R47 R62 R72 = R: COMP: -R-NC_R1608; COMPONENTTYPE: 4; NOTMOUNT: NOT MOUNT; SIZECODESMD: 1608
R20 R29 R39 R48 R63 R73 R97 R104-R106 R111 R127 = R: COMP: -R-RK73Z1JTTD; COMPONENTTYPE: 4; SIZECODESMD: 1608; VAL1: 0; VAL2: 1A
R21 R31 R40 R50 = R: COMP: -R-RK73H2ATTD1500F; COMPONENTTYPE: 4; SIZECODESMD: 2012; VAL1: 150(F); VAL2: 250mW
R23 R32 R41 R51 R65 R66 R75 R76 = R: COMP: -R-ERJ6DQF3R3V; COMPONENTTYPE: 4; SIZECODESMD: 2012; VAL1: 3.3(F); VAL2: 500mW
U?#5 = WAKU_DEF100: COMPONENTTYPE: 2; DATE: 2022/03/07; DRAWINGNUMBER: RD172-SCHEMATIC-01; FUNCTION: 3 Level PFC Switching; REVISION: 01; SAVEAREA0: 148187,-66180,486823,89919; SAVECOUNT: 6; SHEETNUMBER: 2/7; TITLE: T-type 3 Level 1.6kW PFC for Server; UPDATEDATE: 2022/03/07; UPDATETIME: 09:34:24
C48 C49 C54 C55 = CP: COMP: -C-LGW2E102MELC35; COMPONENTTYPE: 4; VAL1: 1000u(M); VAL2: 250V
C110-C115 = C: COMP: -C-C5750X6S2W225K250KA; COMPONENTTYPE: 4; VAL1: 2.2u(K); VAL2: 450V
D17 D19 = SBD: COMP: -D-CMS04_TE12L_Q_AC; COMPONENTTYPE: 4; USERCOMPTEXT3: TOSHIBA; VAL1: CMS04(TE12L,Q,M); VAL3: CMS04(TE12L,Q,M)
Q7 = TK62N60W5,S1VF: COMP: -Q-TK62N60W5; COMPONENTTYPE: 4; INSTANCENAME: INS18652567; USERCOMPTEXT3: TOSHIBA
Q8 = TK62N60W5,S1VF: COMP: -Q-TK62N60W5; COMPONENTTYPE: 4; INSTANCENAME: INS18652910; USERCOMPTEXT3: TOSHIBA
R56 R61 = R: COMP: -R-352227KFT; COMPONENTTYPE: 4; SIZECODESMD: 6432; VAL1: 75k(F); VAL2: 3W
R64 R77 = R: COMP: -R-ERJ3EKF1202V; COMPONENTTYPE: 4; SIZECODESMD: 1608; VAL1: 12k(F); VAL2: 100mW
TB4 = OT_264: COMP: -TB-OT-264; COMPONENTTYPE: 4; INSTANCENAME: INS18174423; PART TYPE: Terminal Block; REFERENCE TEMPLATE: TB; SAVECOUNT: 1; SIZE: 1; UPDATEDATE: 2021/12/22; UPDATETIME: 16:53:54
TB5 = OT_264: COMP: -TB-OT-264; COMPONENTTYPE: 4; INSTANCENAME: INS18174903; PART TYPE: Terminal Block; REFERENCE TEMPLATE: TB; SAVECOUNT: 1; SIZE: 1; UPDATEDATE: 2021/12/22; UPDATETIME: 16:53:54
U?#4 = WAKU_DEF100: COMPONENTTYPE: 2; DATE: 2022/03/07; DRAWINGNUMBER: RD172-SCHEMATIC-01; FUNCTION: 3 Level PFC Switching; REVISION: 01; SAVEAREA0: 148187,-66180,486823,89919; SAVECOUNT: 6; SHEETNUMBER: 3/7; TITLE: T-type 3 Level 1.6kW PFC for Server; UPDATEDATE: 2022/03/07; UPDATETIME: 09:34:24
C70 C73 = C: COMP: -C-GCM1555C1H270FA16D; COMPONENTTYPE: 4; SIZECODESMD: 1005; VAL1: 27p(F); VAL2: 50V
C74 C87 C93 C99 = C: COMP: -C-GRM1885C1H102JA01D; COMPONENTTYPE: 4; SIZECODESMD: 1608; VAL1: 1000p(J); VAL2: 50V
CN7 = BM02B_PASS_TFT_LF__SN: COMP: -CN-BM02B-PASS-TFT_LF_SN; COMPONENTTYPE: 4; INSTANCENAME: INS18317090; PART TYPE: PA Connector; REFERENCE TEMPLATE: CN; SAVECOUNT: 1; SIZE: 1; UPDATEDATE: 2021/12/22; UPDATETIME: 16:53:54
D22 = DEW: COMP: -D-1SS423_TE85L_F_AC; COMPONENTTYPE: 4; USERCOMPTEXT3: TOSHIBA; VAL1: 1SS423(TE85L,F); VAL3: 1SS423(TE85L,F)
IC13 IC17 = OPA4325IPWR_4: COMP: -IC-OPA4325IPWR; COMPONENTTYPE: 8; CaptureCellPackProp: OPA4325IPWR_4A; FUNCN: OPA4325IPWR_1; VAL1: OPA4325IPWR; VAL3: OPA4325IPWR
R78 R80 = R: COMP: -R-ERA3AEB103V; COMPONENTTYPE: 4; SIZECODESMD: 1608; VAL1: 10k(B); VAL2: 100mW
R79 R81 = R: COMP: -R-ERA3AEB203V; COMPONENTTYPE: 4; SIZECODESMD: 1608; VAL1: 30k(B); VAL2: 100mW
R82 = R: COMP: -R-ERJ3EKF2201V; COMPONENTTYPE: 4; SIZECODESMD: 1608; VAL1: 2.2k(F); VAL2: 100mW
R84 = R: COMP: -R-RK73H1ETTP1003F; COMPONENTTYPE: 4; SIZECODESMD: 1005; VAL1: 100k(F); VAL2: 100mW
U?#3 = WAKU_DEF100: COMPONENTTYPE: 2; DATE: 2022/03/07; DRAWINGNUMBER: RD172-SCHEMATIC-01; FUNCTION: Current Detection,Thermal Detection; REVISION: 01; SAVEAREA0: 148187,-66180,486823,89919; SAVECOUNT: 6; SHEETNUMBER: 4/7; TITLE: T-type 3 Level 1.6kW PFC for Server; UPDATEDATE: 2022/03/07; UPDATETIME: 09:34:24
C88 C89 = C: COMP: -C-GRM1882C1H222JA01D; COMPONENTTYPE: 4; SIZECODESMD: 1608; VAL1: 2200p(J); VAL2: 50V
C94 C95 C97 C100 = C: COMP: -C-GRM1555C1H102JA01D; COMPONENTTYPE: 4; SIZECODESMD: 1005; VAL1: 1000p(J); VAL2: 50V
IC14 = REF2025AIDDCT: COMP: -IC-REF2025AIDDCT; COMPONENTTYPE: 4; SAVEAREA0: -3467,-13658,20665,4033; SAVECOUNT: 2; UPDATEDATE: 2021/12/27; UPDATETIME: 16:09:37
IC15 IC16 IC18 = TLP7920_D4ALF1_F_0: COMP: -IC-TLP7920_LF5_TP5; COMPONENTTYPE: 4; USERCOMPTEXT3: TOSHIBA
L5-L7 = ACT1210_101_2P_TL00: COMP: -L-ACT1210-101-2P-TL00; COMPONENTTYPE: 4; INSTANCENAME: INS18165735; SAVECOUNT: 1; UPDATEDATE: 2021/12/22; UPDATETIME: 16:53:54; VAL1: 100uH; VAL2: 150mA
L8-L10 = L: COMP: -L-LQW15CA22NK00; COMPONENTTYPE: 4; SIZECODESMD: 1005; VAL1: 22n(K); VAL2: 1.3A; VAL3: LQW15CA22NK00D
R87 R100 R101 R114 R115 R128 = R: COMP: -R-NC_R1005; COMPONENTTYPE: 4; NOTMOUNT: NOT MOUNT; SIZECODESMD: 1005
R88-R93 R102 R103 R109 R117-R121 R125 = R: COMP: -R-ERA3AEB184V; COMPONENTTYPE: 4; SIZECODESMD: 1608; VAL1: 180k(B); VAL2: 100mW
R94 R110 R122 = R: COMP: -R-ERA3AEB431V; COMPONENTTYPE: 4; SIZECODESMD: 1608; VAL1: 430(B); VAL2: 100mW
R95 R98 R107 R112 R116 R123 = R: COMP: -R-ERA3ARB273V; COMPONENTTYPE: 4; SIZECODESMD: 1608; VAL1: 27k(B); VAL2: 100mW
R96 R99 = R: COMP: -R-ERA3AEB393V; COMPONENTTYPE: 4; SIZECODESMD: 1608; VAL1: 39k(B); VAL2: 100mW
R22 R43 R57 R108 R113 R124 R126 = R: COMP: -R-ERA3ARB823V; COMPONENTTYPE: 4; SIZECODESMD: 1608; VAL1: 82k(B); VAL2: 100mW
U?#2 = WAKU_DEF100: COMPONENTTYPE: 2; DATE: 2022/03/07; DRAWINGNUMBER: RD172-SCHEMATIC-01; FUNCTION: Voltage Detection; REVISION: 01; SAVEAREA0: 148187,-66180,486823,89919; SAVECOUNT: 6; SHEETNUMBER: 5/7; TITLE: T-type 3 Level 1.6kW PFC for Server; UPDATEDATE: 2022/03/07; UPDATETIME: 09:34:23
C11 = CP: COMP: -C-EEHZC1V680XP; COMPONENTTYPE: 4; VAL1: 68u(M); VAL2: 35V
C80 C84 C101 C105 = C: COMP: -C-GRM188D71A106KA73D; COMPONENTTYPE: 4; SIZECODESMD: 1608; VAL1: 10u(K); VAL2: 10V
IC2 IC6 IC9 = LP2951D: COMP: -IC-LP2951D; COMPONENTTYPE: 4
L4 = L: COMP: -L-MBKK1608T1R0M; COMPONENTTYPE: 4; SIZECODESMD: 1608; VAL1: 1uH(M); VAL2: 1.15A; VAL3: MBKK1608T1R0M
PS1 = PSK_S10C_24: COMP: -PS-PSK-S10C-24; COMPONENTTYPE: 4
PS3 PS5 PS7 = R24P209D: COMP: -PS-R24P209D; COMPONENTTYPE: 4
PS9 = MGFS102405: COMP: -PS-MGFS102405_PIN; COMPONENTTYPE: 4
PS10 PS11 = H0505S_1WR2: COMP: -PS-H0505S-1WR2; COMPONENTTYPE: 4
R24 R25 R44 R45 R58 R59 = R: COMP: -R-ERA3APB623V; COMPONENTTYPE: 4; SIZECODESMD: 1608; VAL1: 62k(B); VAL2: 100mW
R27 R46 R60 = R: COMP: -R-RK73H1JTTD1802F; COMPONENTTYPE: 4; SIZECODESMD: 1608; VAL1: 18k(F); VAL2: 100mW
R86 R129 = R: COMP: -R-RK73B1JTTD473J; COMPONENTTYPE: 4; SIZECODESMD: 1608; VAL1: 47k(J); VAL2: 100mW
U?#1 = WAKU_DEF100: AUTHOR: t5459927; COMPONENTTYPE: 2; DATE: 2022/03/07; DRAWINGNUMBER: RD172-SCHEMATIC-01; FUNCTION: Insulated Power Supply; REVISION: 01; SAVEAREA0: -45080,-4508,463680,304612; SHEETNUMBER: 6/7; TIME: 16:20:58; TITLE: T-type 3 Level 1.6kW PFC for Server; UPDATEDATE: 2022/03/07; UPDATETIME: 09:34:25
ZD1 = ZD: COMP: -D-SMBJ30A_AC; COMPONENTTYPE: 4; VAL1: SMBJ30A; VAL3: SMBJ30A
C107 C108 = C: COMP: -C-NC_C1608; COMPONENTTYPE: 4; NOTMOUNT: NOT MOUNT; SIZECODESMD: 1608
CN8 = WR_60S_VFH05_N1: COMP: -CN-WR-60S-VFH05-N1; COMPONENTTYPE: 4
IC19 = 74VHC541FT_0: COMP: -IC-74VHC541FT; COMPONENTTYPE: 4; SAVEAREA0: -22847,-24597,51708,30063; SAVECOUNT: 2; UPDATEDATE: 2021/12/27; UPDATETIME: 14:50:23; USERCOMPTEXT3: TOSHIBA
IC20 = 74VHC540FT: COMP: -IC-74VHC540FT; COMPONENTTYPE: 4; SAVEAREA0: -22628,-27657,51926,27001; SAVECOUNT: 2; UPDATEDATE: 2021/12/27; UPDATETIME: 14:48:47; USERCOMPTEXT3: TOSHIBA
LED1 LED3 = VCDG1111C_4BY3C_TR: COMP: -LED-VCDG1111C-4BY3C-TR_AC; COMPONENTKIND: 104; COMPONENTTYPE: 4; INSTANCENAME: INS18172566; SIZECODESMD: 1608
LED4 LED5 = VFHR1111C_3BY2A_TR: COMP: -LED-VFHR1111C-3BY2A-TR_AC; COMPONENTKIND: 104; COMPONENTTYPE: 4; INSTANCENAME: INS18256251; SIZECODESMD: 1608
R137 R138 = R: COMP: -R-ERJ3EKF6200V; COMPONENTTYPE: 4; SIZECODESMD: 1608; VAL1: 620(F); VAL2: 100mW
R139 R140 = R: COMP: -R-ERJ3EKF1000V; COMPONENTTYPE: 4; SIZECODESMD: 1608; VAL1: 100(F); VAL2: 100mW
U?#7 = WAKU_DEF100: COMPONENTTYPE: 2; DATE: 2022/03/07; DRAWINGNUMBER: RD172-SCHEMATIC-01; FUNCTION: Contoroller; REVISION: 01; SHEETNUMBER: 7/7; TITLE: T-type 3 Level 1.6kW PFC for Server; UPDATEDATE: 2022/03/07; UPDATETIME: 09:34:25

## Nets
5V: C14.1 C23.1 C31.1 C40.1 C56.1 C65.1 C71.1 C72.1 C77.1 C79.1 C83.1 C84.1 C86.1 C91.1 C92.1 C98.1 C104.1 C105.1 C106.1 C109.1 CN8.1 CN8.2 CN8.3 CN8.4 CT1.Vcc(VCC) D22.C IC1.15(VCC1) IC3.15(VCC1) IC5.15(VCC1) IC7.15(VCC1) IC10.15(VCC1) IC12.15(VCC1) IC13.4(V+) IC14.3(EN) IC14.4(VIN) IC15.8(VDD2) IC16.8(VDD2) IC17.4(V+) IC18.8(VDD2) IC19.20(VCC) IC20.20(VCC) LED4.A LED5.A PS9.+Vout(+VOUT) PS10.1(VIN) PS11.1(VIN) R19.2 R20.2 R28.2 R29.2 R38.2 R39.2 R47.2 R48.2 R62.2 R63.2 R72.2 R73.2 R82.2 R85.1 R130.2 R131.2 R132.2 R133.2 R134.2 R135.2 R136.2 R141.2 TP49.1
24V: C4.1 C10.1 C11.1(2) C17.1 C35.1 C50.1 C76.1 D2.C L4.1 PS1.4(+Vo) PS3.1(+VIN) PS5.1(+VIN) PS7.1(+VIN) R11.1 R12.1 R13.2 RLY2.2 TP7.1 TP48.1 ZD1.C
+5V_AC: C80.1 C81.1 C82.1 C85.1 D23.C IC15.1(VDD1) PS10.7(+VO) R86.2 TP54.1
+5V_DC: C90.1 C96.1 C101.1 C102.1 C103.1 D24.C D25.C IC16.1(VDD1) IC18.1(VDD1) PS11.7(+VO) R129.2 TP63.1
+15V_M: C53.1 C57.1 C58.1 C66.1 C67.1 IC9.1(OUTPUT) IC10.5(VCC2) IC12.5(VCC2) R57.2 TP33.1
+15V_N: C32.1 C33.1 C38.1 C41.1 C42.1 IC5.5(VCC2) IC6.1(OUTPUT) IC7.5(VCC2) R43.2 TP27.1
+15V_P: C15.1 C16.1 C21.1 C24.1 C25.1 IC1.5(VCC2) IC2.1(OUTPUT) IC3.5(VCC2) R22.2 TP17.1
GND: C14.2 C23.2 C31.2 C40.2 C56.2 C65.2 C71.2 C72.2 C74.2 C75.2 C77.2 C78.2 C79.2 C83.2 C84.2 C86.2 C91.2 C92.2 C95.1 C98.2 C100.1 C104.2 C105.2 C106.2 C107.2 C108.2 C109.2 CN7.2 CN8.5 CN8.6 CN8.7 CN8.8 CN8.11 CN8.12 CN8.15 CN8.16 CN8.19 CN8.20 CN8.23 CN8.24 CN8.31 CN8.32 CN8.39 CN8.40 CN8.50 CN8.59 CN8.60 CT1.GND D22.A IC1.9(GND1) IC1.16(GND1) IC3.9(GND1) IC3.16(GND1) IC5.9(GND1) IC5.16(GND1) IC7.9(GND1) IC7.16(GND1) IC10.9(GND1) IC10.16(GND1) IC12.9(GND1) IC12.16(GND1) IC13.11(V-) IC14.2(GND) IC17.11(V-) IC19.1(OE1) IC19.9(A8) IC19.10(GND) IC19.19(OE2) IC20.1(OE1) IC20.3(A2) IC20.4(A3) IC20.5(A4) IC20.6(A5) IC20.7(A6) IC20.8(A7) IC20.9(A8) IC20.10(GND) IC20.19(OE2) L8.1 L9.1 L10.1 LED3.C PC2.3(K) PS9.-Vout(-VOUT) PS10.2(GND) PS11.2(GND) R15.2 R84.1 R113.1 R126.1 TP43.1 TP50.1 TP56.1 TP65.1
GND_5VAC: C80.2 C81.2 C82.2 C85.2 IC15.4(GND1) PS10.5(0V) R86.1 R97.2 TP55.1
GND_5VDC: C90.2 C96.2 C101.2 C102.2 C103.2 IC16.4(GND1) IC18.4(GND1) PS11.5(0V) R111.2 R127.2 R129.1 TP64.1
GND_24V: C4.2 C10.2 C11.2(1) C17.2 C35.2 C50.2 C76.2 LED1.C PS1.3(-Vo) PS3.2(-VIN) PS5.2(-VIN) PS7.2(-VIN) PS9.-Vin(-VIN) Q2.S R17.1 TP9.1 TP53.1 ZD1.A
GND_M: C51.2 C52.2 C53.2 C57.2 C58.2 C59.2 C60.2 C66.2 C67.2 C68.1 C69.2 CN5.G1 CN5.G2 CN6.G1 CN6.G2 D18.A D20.A IC9.3(SHUTDOWN) IC9.4(GND) IC10.1(VEE2) IC10.3(GND2) IC10.8(VEE2) IC12.1(VEE2) IC12.3(GND2) IC12.8(VEE2) PS7.5(-VOUT) Q7.S Q8.S R60.1 R67.1 R74.2 TP37.1
GND_N: C32.2 C33.2 C34.2 C36.2 C37.2 C38.2 C39.2 C41.2 C42.2 C43.1 CN3.G1 CN3.G2 CN4.G1 CN4.G2 D13.A IC5.1(VEE2) IC5.3(GND2) IC5.8(VEE2) IC6.3(SHUTDOWN) IC6.4(GND) IC7.1(VEE2) IC7.2(DESAT) IC7.3(GND2) IC7.8(VEE2) PS5.5(-VOUT) Q5.S Q6.S1 Q6.S2 Q6.S3 R42.1 R46.1 R49.2 TP28.1
GND_P: C15.2 C16.2 C18.2 C19.2 C20.2 C21.2 C22.2 C24.2 C25.2 C26.1 CN1.G1 CN1.G2 CN2.G1 CN2.G2 D8.A IC1.1(VEE2) IC1.3(GND2) IC1.8(VEE2) IC2.3(SHUTDOWN) IC2.4(GND) IC3.1(VEE2) IC3.2(DESAT) IC3.3(GND2) IC3.8(VEE2) PS3.5(-VOUT) Q3.S Q4.S1 Q4.S2 Q4.S3 R26.1 R27.1 R30.2 TP19.1
/DI0_BO: CN8.51 R139.2
/DI1_BO: CN8.52 R140.2
/DO1_BI: CN8.42 IC20.2(A1) R141.1
/DO3_BI: CN8.44 IC19.6(A5) R133.1
/FLT: C108.1 IC1.13(FLT) IC3.13(FLT) IC5.13(FLT) IC7.13(FLT) IC10.13(FLT) IC12.13(FLT) IC19.8(A7) R135.1 TP67.1
/PWM1A_BI: CN8.25 IC19.2(A1) R136.1
/PWM1B_BI: CN8.26 IC19.3(A2) R130.1
/PWM2A_BI: CN8.27 IC19.4(A3) R131.1
/PWM2B_BI: CN8.28 IC19.5(A4) R132.1
/PWM_MA: IC10.11(IN-) IC19.17(Y2) R62.1 TP69.1
/PWM_MB: IC12.11(IN-) IC19.16(Y3) R72.1 TP70.1
/PWM_N: IC5.11(IN-) IC7.11(IN-) IC19.15(Y4) R38.1 R47.1 TP71.1
/PWM_P: IC1.11(IN-) IC3.11(IN-) IC19.18(Y1) R19.1 R28.1 TP68.1
/RESET: IC1.14(RST) IC3.14(RST) IC5.14(RST) IC7.14(RST) IC10.14(RST) IC12.14(RST) IC19.14(Y5) TP72.1
AC_L2: C6.1 C7.1 D7.A D12.C R4.2 R5.2 RLY2.3 TP2.1
AC_L_IN: C3.1 C120.1 L2.2 PS1.2(AC(L)) R1.1 R2.1 R88.1 RLY2.4 TP10.1
AC_N2: C87.2 CT1.8 CT1.9 CT1.10 L3.1 L5.2 R94.1 R100.1
AC_N_IN: C3.2 C6.2 C7.2 C121.1 CT1.1 CT1.2 CT1.3 L2.4 PS1.1(AC(N)) TP8.1
AD0: C88.2 CN8.9 IC17.14 R96.2 TP58.1
AD1: CN8.10 IC13.8 IC13.9 TP47.1
AD2: C70.2 CN8.13 IC13.14 R79.2 TP46.1
AD4: C94.2 CN8.17 IC17.1(OUT) R108.2 TP59.1
AD6: C97.2 CN8.21 IC17.7 R124.2 TP62.1
FG: C8.2 C9.2 C120.2 C121.2 C122.2 C123.2 TB3.1 TB3.2
MAINRLY_5V: IC20.18(Y1) R14.1 TP74.1
RDY: C107.1 IC1.12(RDY) IC3.12(RDY) IC5.12(RDY) IC7.12(RDY) IC10.12(RDY) IC12.12(RDY) IC19.7(A6) R134.1 TP66.1
SIG1: C2.1 C122.1 F1.2 L1.4 R3.2 ZNR1.1
SIG2: C2.2 C123.1 L1.2 R3.1 TB2.1 TB2.2 ZNR1.2
SIG15: PC2.1(A) R14.2 R15.1 TP12.1
SIG19: PC2.6(C) R13.1
SIG20: PC2.4(E) Q2.G R17.2
SIG38: LED4.C R137.2
SIG40: LED5.C R138.2
SIG72: D21.C D29.A
SIG73: D21.A R77.2
SIG74: IC12.6(OUT) R75.1 R76.1
SIG80: D17.C R66.2
SIG81: C60.1 D18.C IC10.2(DESAT) R64.1
SIG82: IC10.6(OUT) R65.1 R66.1
SIG83: IC10.10(IN+) R63.1
SIG86: D16.A R64.2
SIG87: D16.C D28.A
SIG96: D23.A IC15.2(VIN+) L5.4 R87.2 TP57.1
SIG97: IC15.3(VIN-) L5.3 R97.1 R100.2
SIG98: IC15.6(VOUT-) R95.1
SIG99: IC15.7(VOUT+) R98.1
SIG100: IC15.5(GND2) L8.2
SIG108: D24.A IC16.2(VIN+) L6.4 R101.2 TP60.1
SIG110: IC16.6(VOUT-) R107.1
SIG111: IC16.7(VOUT+) R112.1
SIG113: IC16.3(VIN-) L6.3 R111.1 R114.2
SIG116: IC16.5(GND2) L9.2
SIG117: C93.1 L6.1 R101.1 R106.2 R110.2
SIG144: C94.1 IC17.2(IN-) R107.2 R108.1
SIG145: C95.2 IC17.3(IN+) R112.2 R113.2
SIG151: C78.1 IC14.5(VREF) IC17.10 TP51.1
SIG152: C89.2 IC17.12 R98.2 R99.2
SIG174: IC1.10(IN+) R20.1
SIG176: IC1.6(OUT) R21.1 R23.1
SIG178: C22.1 CN1.S D5.A IC1.7(CLAMP) Q3.G R21.2 R26.2 TP18.1
SIG179: D4.C D26.A
SIG181: D9.C R32.2
SIG182: C26.2 CN2.S D9.A IC3.7(CLAMP) Q4.G R30.1 R31.2 TP22.1
SIG183: C20.1 D8.C IC1.2(DESAT) R18.1
SIG184: IC3.6(OUT) R31.1 R32.1
SIG185: D5.C R23.2
SIG186: D4.A R18.2
SIG188: IC3.10(IN+) R29.1
SIG215: C88.1 IC17.13 R95.2 R96.1
SIG217: IC13.1(OUT) IC13.2(IN-) R78.1
SIG220: IC13.6 IC13.7 R80.1
SIG222: C73.1 IC13.12 R80.2 R81.1
SIG235: IC14.1(VBIAS) TP52.1
SIG244: C87.1 L5.1 R87.1 R93.2 R94.2
SIG259: LED3.A R85.2
SIG262: LED1.A R11.2
SIG263: R88.2 R89.1
SIG264: R90.2 R91.1
SIG265: R92.2 R93.1
SIG266: R89.2 R90.1
SIG267: R91.2 R92.1
SIG269: R102.2 R109.1
SIG270: R103.2 R104.1
SIG271: R105.2 R106.1
SIG272: R103.1 R109.2
SIG273: R104.2 R105.1
SIG281: D2.A Q2.D R12.2 RLY2.1 TP11.1
SIG284: C8.1 L1.3 L2.1
SIG286: IC12.10(IN+) R73.1
SIG290: L4.2 PS9.+Vin(+VIN)
SIG308: R24.2 R25.2
SIG309: IC2.7(FEEDBACK) R25.1 R27.2
SIG310: R22.1 R24.1
SIG311: C18.1 C19.1 IC2.8(INPUT) PS3.7(+VOUT)
SIG328: D10.A R37.2
SIG329: D11.C R41.2
SIG331: IC7.10(IN+) R48.1
SIG332: IC5.6(OUT) R40.1 R41.1
SIG333: C43.2 CN4.S D15.A IC7.7(CLAMP) Q6.G R49.1 R50.2 TP31.1
SIG334: C34.1 CN3.S D11.A IC5.7(CLAMP) Q5.G R40.2 R42.2 TP26.1
SIG335: D15.C R51.2
SIG336: D10.C D27.A
SIG338: IC7.6(OUT) R50.1 R51.1
SIG341: IC5.10(IN+) R39.1
SIG343: C39.1 D13.C IC5.2(DESAT) R37.1
SIG347: C99.1 L7.1 R115.1 R122.2 R125.2
SIG353: C100.2 IC17.5 R116.2 R126.2
SIG354: IC18.7(VOUT+) R116.1
SIG356: D25.A IC18.2(VIN+) L7.4 R115.2 TP61.1
SIG357: IC18.6(VOUT-) R123.1
SIG358: IC18.5(GND2) L10.2
SIG359: IC18.3(VIN-) L7.3 R127.1 R128.2
SIG363: R121.2 R125.1
SIG364: R120.2 R121.1
SIG365: R118.2 R119.1
SIG366: R119.2 R120.1
SIG367: R117.2 R118.1
SIG368: C97.1 IC17.6 R123.2 R124.1
SIG372: R43.1 R44.1
SIG374: C36.1 C37.1 IC6.8(INPUT) PS5.7(+VOUT)
SIG376: R44.2 R45.2
SIG377: IC6.7(FEEDBACK) R45.1 R46.2
SIG378: IC9.7(FEEDBACK) R59.1 R60.2
SIG380: R57.1 R58.1
SIG382: R58.2 R59.2
SIG383: C51.1 C52.1 IC9.8(INPUT) PS7.7(+VOUT)
Vdc_M: D6.A D14.C D27.C D28.C L3.2 Q4.D1 Q4.D2 Q4.D3 Q4.D4 Q5.D Q7.D
Vdc_M_dct: C48.2(1) C49.2(1) C54.1(2) C55.1(2) C110.2 C111.1 C112.2 C113.1 C114.2 C115.1 D29.C Q8.D R56.1 R61.2 R102.1
Vdc_N: C54.2(1) C55.2(1) C93.2 C99.2 C111.2 C113.2 C115.2 D12.A D14.A L6.2 L7.2 Q6.D1 Q6.D2 Q6.D3 Q6.D4 R61.1 R110.1 R114.1 R122.1 R128.1 TB5.1 TB5.2
Vdc_P: C48.1(2) C49.1(2) C110.1 C112.1 C114.1 D6.C D7.C D26.C Q3.D R56.2 R117.1 TB4.1 TB4.2
Vo_Isen: CT1.Vo IC13.5 TP44.1
Vref_in: C73.2 C89.1 IC17.8 IC17.9 R81.2 R99.1
Vref_Isen: CT1.Vref IC13.3(IN+) TP45.1
N18174803: C68.2 CN6.S D19.A IC12.7(CLAMP) Q8.G R74.1 R75.2 TP42.1
N18174813: C59.1 CN5.S D17.A IC10.7(CLAMP) Q7.G R65.2 R67.2 TP36.1
N18175764: D19.C R76.2
N18175788: C69.1 D20.C IC12.2(DESAT) R77.1
N18186220: IC19.13(Y6) R137.1 R139.1
N18186262: IC19.12(Y7) R138.1 R140.1
N18188625: F1.1 TB1.1 TB1.2
N18188901: C9.1 L1.1 L2.3
N18316829: C70.1 IC13.13 R78.2 R79.1
N18317079: C74.1 D22.C/A(AC) IC13.10 R83.1
N18317089: C75.1 CN7.1 R82.1 R83.2 R84.2
N18876199: R1.2 R4.1
N18876231: R2.2 R5.1

Not connected (* = marked no-connect by the designer): CN7 NC1(PAD1) NC2(PAD2); CN8 14 18 22 29 30 33 34 35 36 37 38 41 43 45 46 47 48 49 53 54 55 56 57 58; IC1 4(NC); IC2 2(SENSE) 5(ERROR) 6(VTAP); IC3 4(NC); IC5 4(NC); IC6 2(SENSE) 5(ERROR) 6(VTAP); IC7 4(NC); IC9 2(SENSE) 5(ERROR) 6(VTAP); IC10 4(NC); IC12 4(NC); IC19 11(Y8); IC20 11(Y8) 12(Y7) 13(Y6) 14(Y5) 15(Y4) 16(Y3) 17(Y2); PS3 6(COM); PS5 6(COM); PS7 6(COM); PS9 NC(NC1) NC2 RC

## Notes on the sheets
sheet 1
- /RDY
- FLT
- 5V
- 24V
sheet 3
- FC=1.9MHz
- AC Voltage Detection
- Fc = 370kHz
- FC=1.9MHz
- FC=1.9MHz
- Mid. DC Voltage
  Detection
- Fc = 370kHz
- FC=1.9MHz
- FC=1.9MHz
- DC Voltage Detection
- Fc = 370kHz
- FC=1.9MHz
- Vref in 2.5V
sheet 4
- Fc = 204kHz
- Current Detection
- Vref in 2.5V
- Thermal. Detection
- THERMISTOR
- EC2F103A2-40113
sheet 5
- Output
  DC380V
sheet 7
- Input AC90-264V
- AC_L
- AC_N
- FG
